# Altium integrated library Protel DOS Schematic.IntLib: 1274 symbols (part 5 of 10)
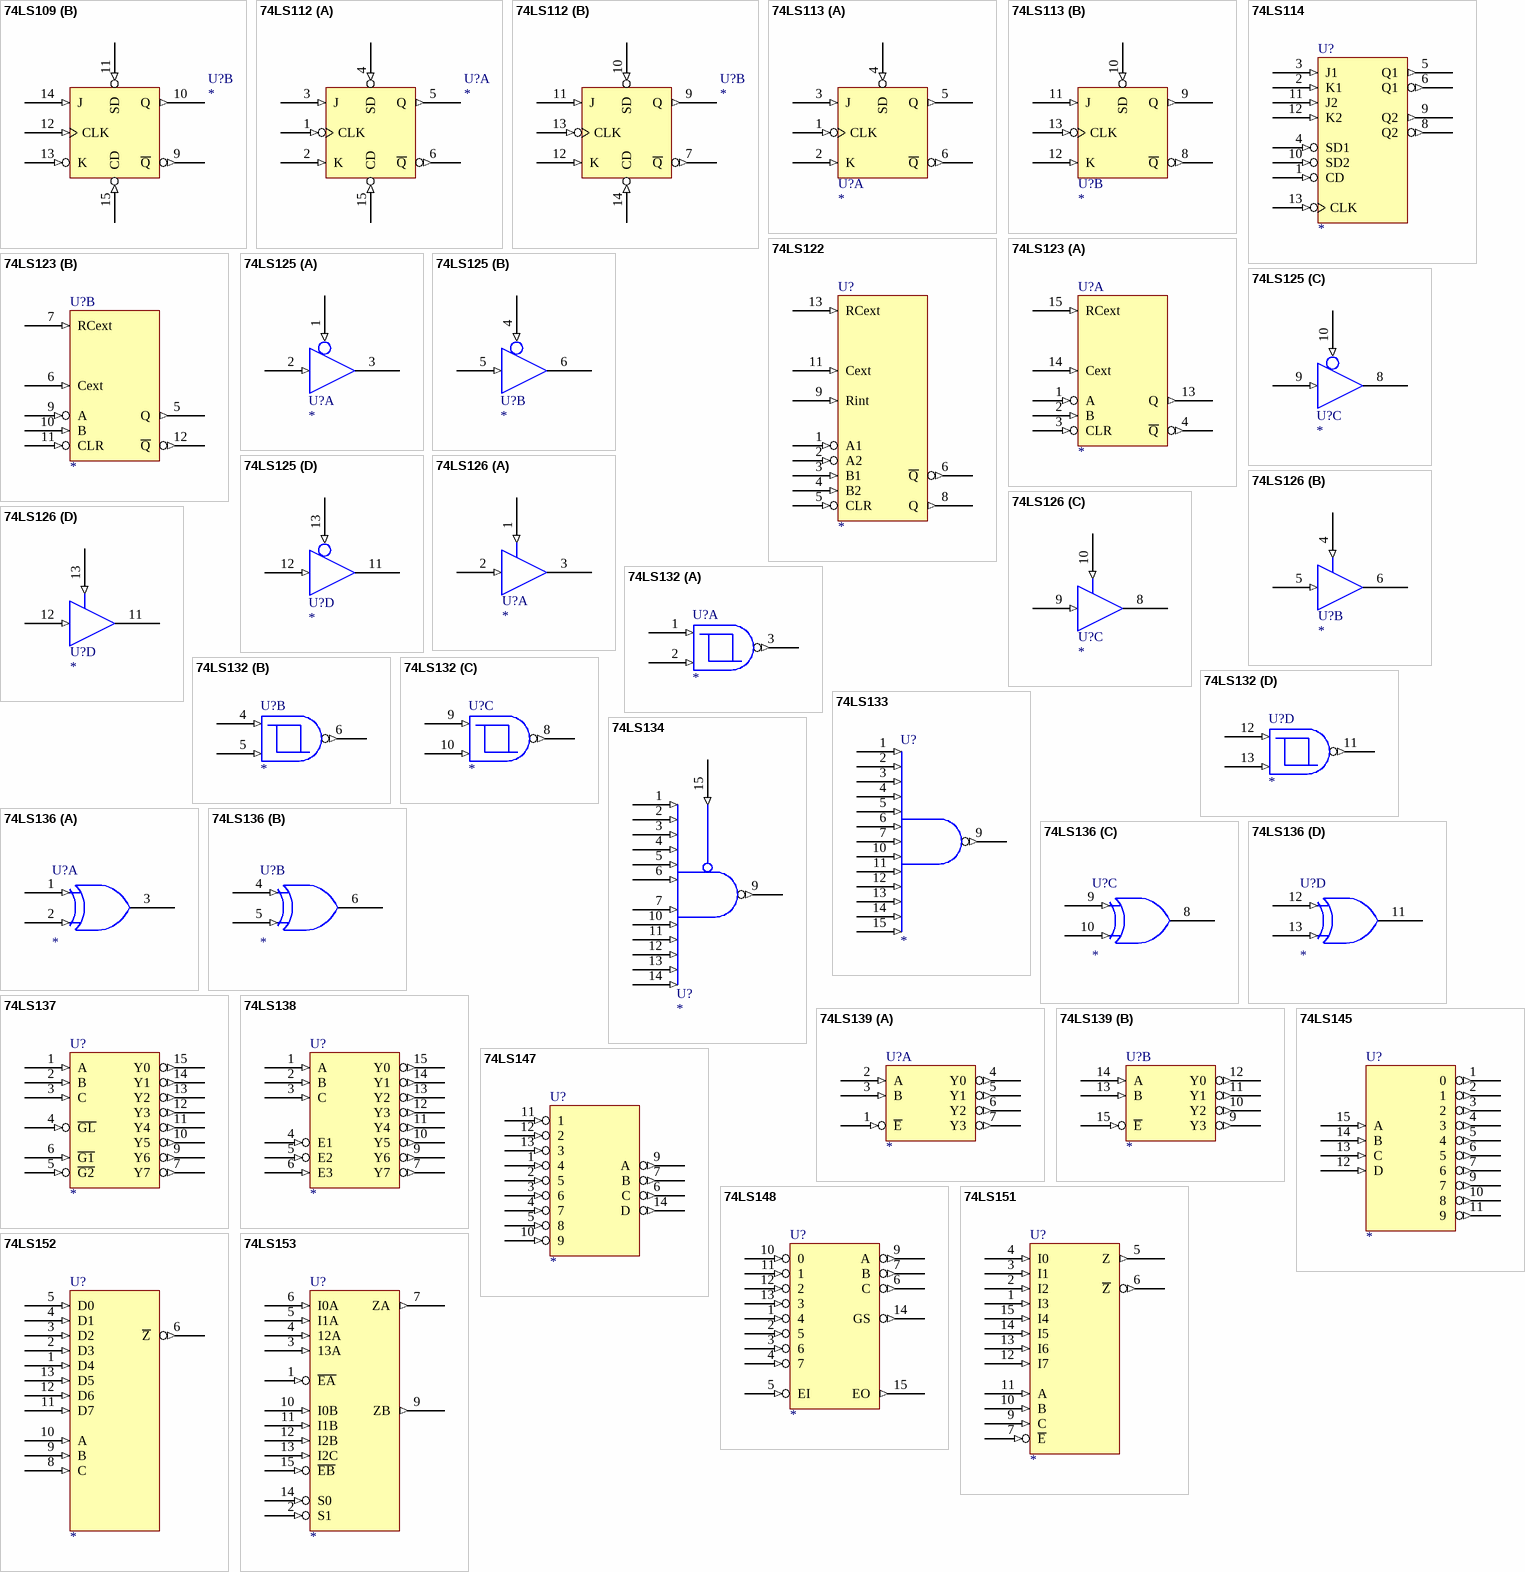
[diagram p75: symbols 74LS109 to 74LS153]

## 74LS125
designator U?
footprint DIP-14
part A pins: 1 (in), 2 (in), 3 (hiz), 7 GND (power) hidden to GND, 14 VCC (power) hidden to VCC
part B pins: 4 (in), 5 (in), 6 (hiz), 7 GND (power) hidden to GND, 14 VCC (power) hidden to VCC
part C pins: 7 GND (power) hidden to GND, 8 (hiz), 9 (in), 10 (in), 14 VCC (power) hidden to VCC
part D pins: 7 GND (power) hidden to GND, 11 (hiz), 12 (in), 13 (in), 14 VCC (power) hidden to VCC
2 alternate drawings of the same symbol

## 74LS126
designator U?
footprint DIP-14
part A pins: 1 (in), 2 (in), 3 (hiz), 7 GND (power) hidden to GND, 14 VCC (power) hidden to VCC
part B pins: 4 (in), 5 (in), 6 (hiz), 7 GND (power) hidden to GND, 14 VCC (power) hidden to VCC
part C pins: 7 GND (power) hidden to GND, 8 (hiz), 9 (in), 10 (in), 14 VCC (power) hidden to VCC
part D pins: 7 GND (power) hidden to GND, 11 (hiz), 12 (in), 13 (in), 14 VCC (power) hidden to VCC
2 alternate drawings of the same symbol

## 74LS132
designator U?
footprint DIP-14
part A pins: 1 (in), 2 (in), 3 (out), 7 GND (power) hidden to GND, 14 VCC (power) hidden to VCC
part B pins: 4 (in), 5 (in), 6 (out), 7 GND (power) hidden to GND, 14 VCC (power) hidden to VCC
part C pins: 7 GND (power) hidden to GND, 8 (out), 9 (in), 10 (in), 14 VCC (power) hidden to VCC
part D pins: 7 GND (power) hidden to GND, 11 (out), 12 (in), 13 (in), 14 VCC (power) hidden to VCC
2 alternate drawings of the same symbol

## 74LS133
designator U?
footprint DIP-16
pins: 1 (in), 2 (in), 3 (in), 4 (in), 5 (in), 6 (in), 7 (in), 8 GND (power) hidden to GND, 9 (out), 10 (in), 11 (in), 12 (in), 13 (in), 14 (in), 15 (in), 16 VCC (power) hidden to VCC
2 alternate drawings of the same symbol

## 74LS134
designator U?
footprint DIP-16
pins: 1 (in), 2 (in), 3 (in), 4 (in), 5 (in), 6 (in), 7 (in), 8 GND (power) hidden to GND, 9 (out), 10 (in), 11 (in), 12 (in), 13 (in), 14 (in), 15 (in), 16 VCC (power) hidden to VCC
2 alternate drawings of the same symbol

## 74LS136
designator U?
footprint DIP-14
part A pins: 1 (in), 2 (in), 3 (oc), 7 GND (power) hidden to GND, 14 VCC (power) hidden to VCC
part B pins: 4 (in), 5 (in), 6 (oc), 7 GND (power) hidden to GND, 14 VCC (power) hidden to VCC
part C pins: 7 GND (power) hidden to GND, 8 (oc), 9 (in), 10 (in), 14 VCC (power) hidden to VCC
part D pins: 7 GND (power) hidden to GND, 11 (oc), 12 (in), 13 (in), 14 VCC (power) hidden to VCC
2 alternate drawings of the same symbol

## 74LS137
designator U?
footprint DIP-16
pins: 1 A (in), 2 B (in), 3 C (in), 4 ~{GL} (in), 5 ~{G2} (in), 6 ~{G1} (in), 7 Y7 (out), 8 GND (power) hidden to GND, 9 Y6 (out), 10 Y5 (out), 11 Y4 (out), 12 Y3 (out), 13 Y2 (out), 14 Y1 (out), 15 Y0 (out), 16 VCC (power) hidden to VCC
2 alternate drawings of the same symbol

## 74LS138
designator U?
footprint DIP-16
pins: 1 A (in), 2 B (in), 3 C (in), 4 E1 (in), 5 E2 (in), 6 E3 (in), 7 Y7 (out), 8 GND (power) hidden to GND, 9 Y6 (out), 10 Y5 (out), 11 Y4 (out), 12 Y3 (out), 13 Y2 (out), 14 Y1 (out), 15 Y0 (out), 16 VCC (power) hidden to VCC
2 alternate drawings of the same symbol

## 74LS139
designator U?
footprint DIP-16
part A pins: 1 ~{E} (in), 2 A (in), 3 B (in), 4 Y0 (out), 5 Y1 (out), 6 Y2 (out), 7 Y3 (out), 8 GND (power) hidden to GND, 16 VCC (power) hidden to VCC
part B pins: 8 GND (power) hidden to GND, 9 Y3 (out), 10 Y2 (out), 11 Y1 (out), 12 Y0 (out), 13 B (in), 14 A (in), 15 ~{E} (in), 16 VCC (power) hidden to VCC
2 alternate drawings of the same symbol

## 74LS145
designator U?
footprint DIP-16
pins: 1 0 (out), 2 1 (out), 3 2 (out), 4 3 (out), 5 4 (out), 6 5 (out), 7 6 (out), 8 GND (power) hidden to GND, 9 7 (out), 10 8 (out), 11 9 (out), 12 D (in), 13 C (in), 14 B (in), 15 A (in), 16 VCC (power) hidden to VCC
2 alternate drawings of the same symbol

## 74LS147
designator U?
footprint DIP-16
pins: 1 4 (in), 2 5 (in), 3 6 (in), 4 7 (in), 5 8 (in), 6 C (out), 7 B (out), 8 GND (power) hidden to GND, 9 A (out), 10 9 (in), 11 1 (in), 12 2 (in), 13 3 (in), 14 D (out), 16 VCC (power) hidden to VCC
2 alternate drawings of the same symbol

## 74LS148
designator U?
footprint DIP-16
pins: 1 4 (in), 2 5 (in), 3 6 (in), 4 7 (in), 5 EI (in), 6 C (out), 7 B (out), 8 GND (power) hidden to GND, 9 A (out), 10 0 (in), 11 1 (in), 12 2 (in), 13 3 (in), 14 GS (out), 15 EO (out), 16 VCC (power) hidden to VCC
2 alternate drawings of the same symbol

## 74LS151
designator U?
footprint DIP-16
pins: 1 I3 (in), 2 I2 (in), 3 I1 (in), 4 I0 (in), 5 Z (out), 6 ~{Z} (out), 7 ~{E} (in), 8 GND (power) hidden to GND, 9 C (in), 10 B (in), 11 A (in), 12 I7 (in), 13 I6 (in), 14 I5 (in), 15 I4 (in), 16 VCC (power) hidden to VCC
2 alternate drawings of the same symbol

## 74LS152
designator U?
footprint DIP-14
pins: 1 D4 (in), 2 D3 (in), 3 D2 (in), 4 D1 (in), 5 D0 (in), 6 ~{Z} (out), 7 GND (power) hidden to GND, 8 C (in), 9 B (in), 10 A (in), 11 D7 (in), 12 D6 (in), 13 D5 (in), 14 VCC (power) hidden to VCC
2 alternate drawings of the same symbol

## 74LS153
designator U?
footprint DIP-16
pins: 1 ~{EA} (in), 2 S1 (in), 3 13A (in), 4 12A (in), 5 I1A (in), 6 I0A (in), 7 ZA (out), 8 GND (power) hidden to GND, 9 ZB (out), 10 I0B (in), 11 I1B (in), 12 I2B (in), 13 I2C (in), 14 S0 (in), 15 ~{EB} (in), 16 VCC (power) hidden to VCC
2 alternate drawings of the same symbol

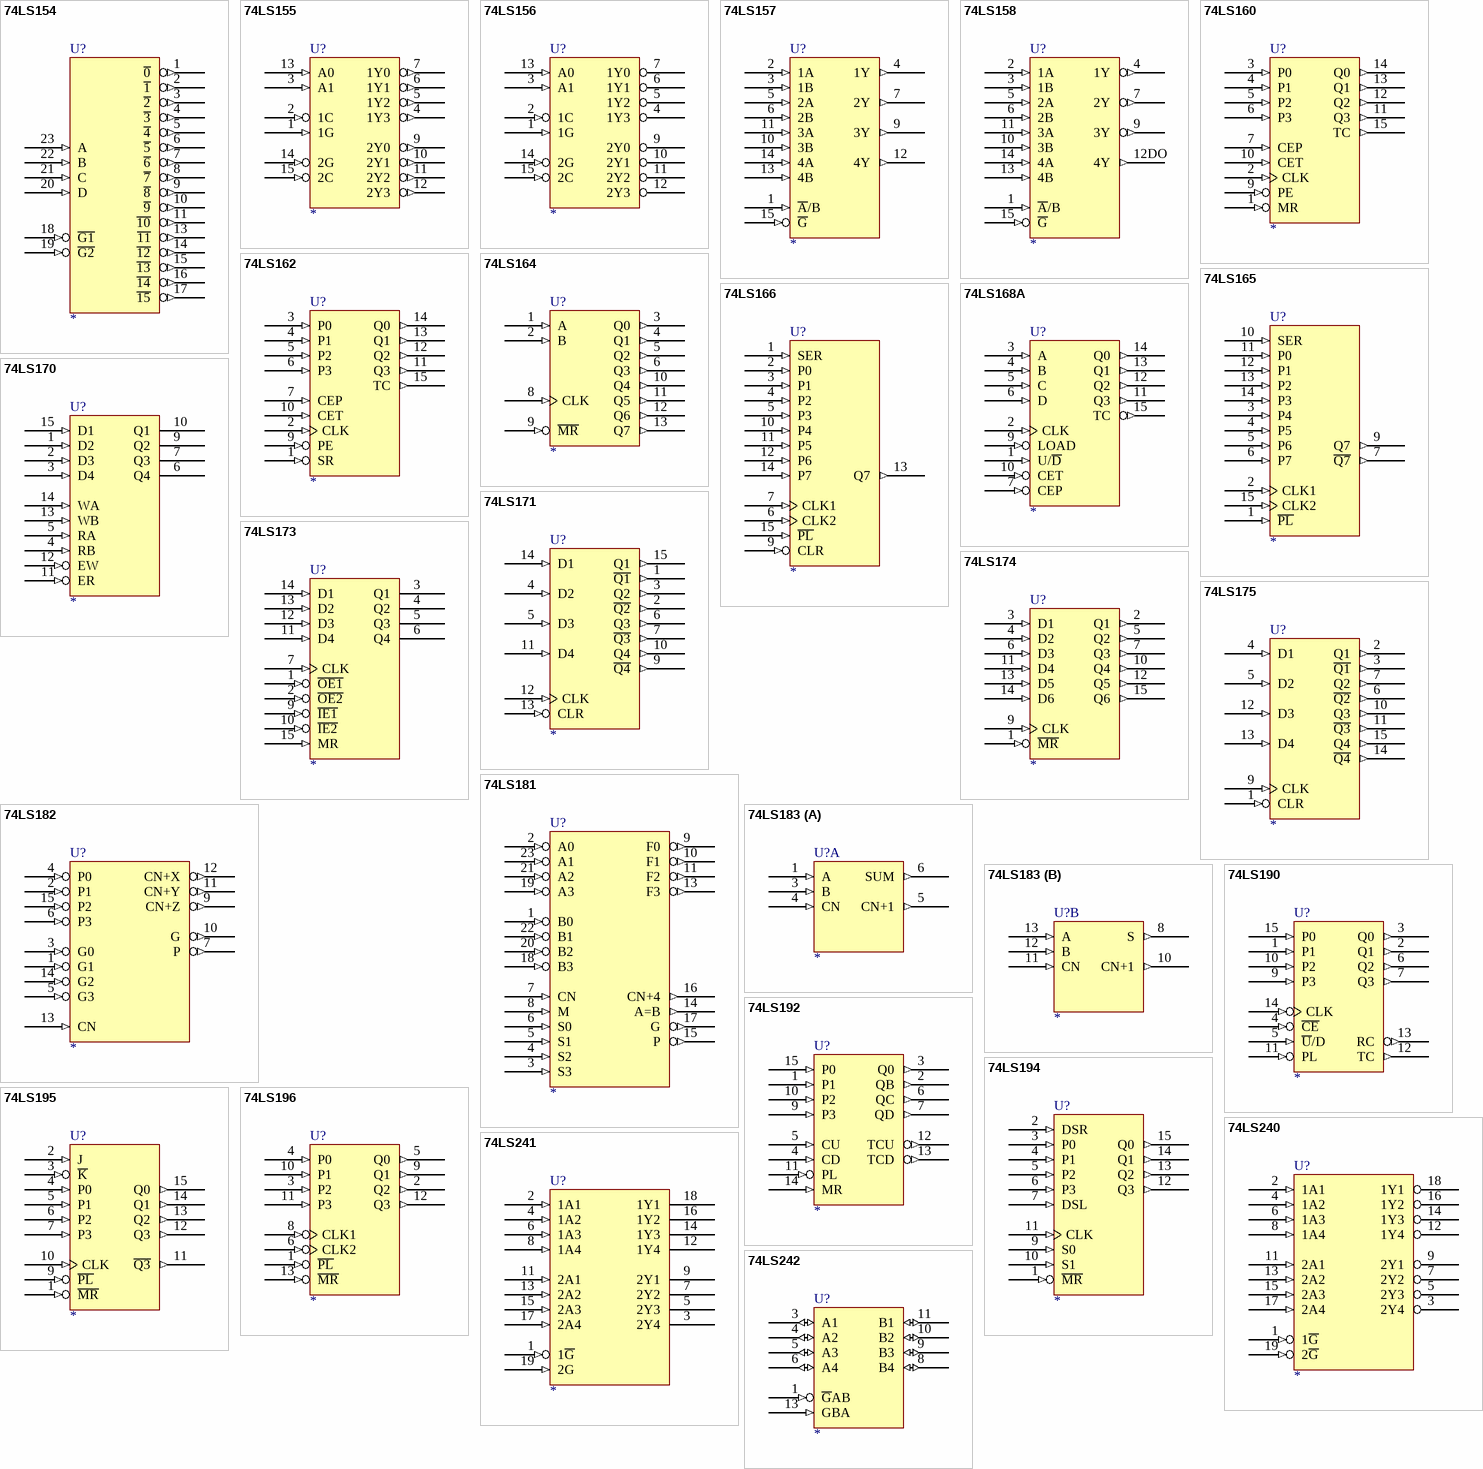
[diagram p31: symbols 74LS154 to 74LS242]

## 74LS154
designator U?
footprint DIP-24
pins: 1 ~{0} (out), 2 ~{1} (out), 3 ~{2} (out), 4 ~{3} (out), 5 ~{4} (out), 6 ~{5} (out), 7 ~{6} (out), 8 ~{7} (out), 9 ~{8} (out), 10 ~{9} (out), 11 ~{10} (out), 12 GND (power) hidden to GND, 13 ~{11} (out), 14 ~{12} (out), 15 ~{13} (out), 16 ~{14} (out), 17 ~{15} (out), 18 ~{G1} (in), 19 ~{G2} (in), 20 D (in), 21 C (in), 22 B (in), 23 A (in), 24 VCC (power) hidden to VCC
2 alternate drawings of the same symbol

## 74LS155
designator U?
footprint DIP-16
pins: 1 1G (in), 2 1C (in), 3 A1 (in), 4 1Y3 (out), 5 1Y2 (out), 6 1Y1 (out), 7 1Y0 (out), 8 GND (power) hidden to GND, 9 2Y0 (out), 10 2Y1 (out), 11 2Y2 (out), 12 2Y3 (out), 13 A0 (in), 14 2G (in), 15 2C (in), 16 VCC (power) hidden to VCC
2 alternate drawings of the same symbol

## 74LS156
designator U?
footprint DIP-16
pins: 1 1G (in), 2 1C (in), 3 A1 (in), 4 1Y3 (oc), 5 1Y2 (oc), 6 1Y1 (oc), 7 1Y0 (oc), 8 GND (power) hidden to GND, 9 2Y0 (oc), 10 2Y1 (oc), 11 2Y2 (oc), 12 2Y3 (oc), 13 A0 (in), 14 2G (in), 15 2C (in), 16 VCC (power) hidden to VCC
2 alternate drawings of the same symbol

## 74LS157
designator U?
footprint DIP-16
pins: 1 ~{A}/B (in), 2 1A (in), 3 1B (in), 4 1Y (out), 5 2A (in), 6 2B (in), 7 2Y (out), 8 GND (power) hidden to GND, 9 3Y (out), 10 3B (in), 11 3A (in), 12 4Y (out), 13 4B (in), 14 4A (in), 15 ~{G} (in), 16 VCC (power) hidden to VCC
2 alternate drawings of the same symbol

## 74LS158
designator U?
footprint DIP-16
pins: 1 ~{A}/B (in), 2 1A (in), 3 1B (in), 4 1Y (out), 5 2A (in), 6 2B (in), 7 2Y (out), 8 GND (power) hidden to GND, 9 3Y (out), 10 3B (in), 11 3A (in), 12DO 4Y (out), 13 4B (in), 14 4A (in), 15 ~{G} (in), 16 VCC (power) hidden to VCC
2 alternate drawings of the same symbol

## 74LS160
designator U?
footprint DIP-16
pins: 1 MR (in), 2 CLK (in), 3 P0 (in), 4 P1 (in), 5 P2 (in), 6 P3 (in), 7 CEP (in), 8 GND (power) hidden to GND, 9 PE (in), 10 CET (in), 11 Q3 (out), 12 Q2 (out), 13 Q1 (out), 14 Q0 (out), 15 TC (out), 16 VCC (power) hidden to VCC
2 alternate drawings of the same symbol

## 74LS162
designator U?
footprint DIP-16
pins: 1 SR (in), 2 CLK (in), 3 P0 (in), 4 P1 (in), 5 P2 (in), 6 P3 (in), 7 CEP (in), 8 GND (power) hidden to GND, 9 PE (in), 10 CET (in), 11 Q3 (out), 12 Q2 (out), 13 Q1 (out), 14 Q0 (out), 15 TC (out), 16 VCC (power) hidden to VCC
2 alternate drawings of the same symbol

## 74LS164
designator U?
footprint DIP-14
pins: 1 A (in), 2 B (in), 3 Q0 (out), 4 Q1 (out), 5 Q2 (out), 6 Q3 (out), 7 GND (power) hidden to GND, 8 CLK (in), 9 ~{MR} (in), 10 Q4 (out), 11 Q5 (out), 12 Q6 (out), 13 Q7 (out), 14 VCC (power) hidden to VCC
2 alternate drawings of the same symbol

## 74LS165
designator U?
footprint DIP-16
pins: 1 ~{PL} (in), 2 CLK1 (in), 3 P4 (in), 4 P5 (in), 5 P6 (in), 6 P7 (in), 7 ~{Q7} (out), 8 GND (power) hidden to GND, 9 Q7 (out), 10 SER (in), 11 P0 (in), 12 P1 (in), 13 P2 (in), 14 P3 (in), 15 CLK2 (in), 16 VCC (power) hidden to VCC
2 alternate drawings of the same symbol

## 74LS166
designator U?
footprint DIP-16
pins: 1 SER (in), 2 P0 (in), 3 P1 (in), 4 P2 (in), 5 P3 (in), 6 CLK2 (in), 7 CLK1 (in), 8 GND (power) hidden to GND, 9 CLR (in), 10 P4 (in), 11 P5 (in), 12 P6 (in), 13 Q7 (out), 14 P7 (in), 15 ~{PL} (in), 16 VCC (power) hidden to VCC
2 alternate drawings of the same symbol

## 74LS168A
designator U?
Synchronous 4-Bit Up/Down Decade Counter
pins: 1 U/~{D} (in), 2 CLK (in), 3 A (in), 4 B (in), 5 C (in), 6 D (in), 7 CEP (in), 8 GND (power) hidden to GND, 9 LOAD (in), 10 CET (in), 11 Q3 (out), 12 Q2 (out), 13 Q1 (out), 14 Q0 (out), 15 TC (out), 16 VCC (power) hidden to VCC
2 alternate drawings of the same symbol

## 74LS170
designator U?
footprint DIP-16
pins: 1 D2 (in), 2 D3 (in), 3 D4 (in), 4 RB (in), 5 RA (in), 6 Q4 (oc), 7 Q3 (oc), 8 GND (power) hidden to GND, 9 Q2 (oc), 10 Q1 (oc), 11 ER (in), 12 EW (in), 13 WB (in), 14 WA (in), 15 D1 (in), 16 VCC (power) hidden to VCC
2 alternate drawings of the same symbol

## 74LS171
designator U?
footprint DIP-16
pins: 1 ~{Q1} (out), 2 ~{Q2} (out), 3 Q2 (out), 4 D2 (in), 5 D3 (in), 6 Q3 (out), 7 ~{Q3} (out), 8 GND (power) hidden to GND, 9 ~{Q4} (out), 10 Q4 (out), 11 D4 (in), 12 CLK (in), 13 CLR (in), 14 D1 (in), 15 Q1 (out), 16 VCC (power) hidden to VCC
2 alternate drawings of the same symbol

## 74LS173
designator U?
footprint DIP-16
pins: 1 ~{OE1} (in), 2 ~{OE2} (in), 3 Q1 (hiz), 4 Q2 (hiz), 5 Q3 (hiz), 6 Q4 (hiz), 7 CLK (in), 8 GND (power) hidden to GND, 9 ~{IE1} (in), 10 ~{IE2} (in), 11 D4 (in), 12 D3 (in), 13 D2 (in), 14 D1 (in), 15 MR (in), 16 VCC (power) hidden to VCC
2 alternate drawings of the same symbol

## 74LS174
designator U?
footprint DIP-16
pins: 1 ~{MR} (in), 2 Q1 (out), 3 D1 (in), 4 D2 (in), 5 Q2 (out), 6 D3 (in), 7 Q3 (out), 8 GND (power) hidden to GND, 9 CLK (in), 10 Q4 (out), 11 D4 (in), 12 Q5 (out), 13 D5 (in), 14 D6 (in), 15 Q6 (out), 16 VCC (power) hidden to VCC
2 alternate drawings of the same symbol

## 74LS175
designator U?
footprint DIP-16
pins: 1 CLR (in), 2 Q1 (out), 3 ~{Q1} (out), 4 D1 (in), 5 D2 (in), 6 ~{Q2} (out), 7 Q2 (out), 8 GND (power) hidden to GND, 9 CLK (in), 10 Q3 (out), 11 ~{Q3} (out), 12 D3 (in), 13 D4 (in), 14 ~{Q4} (out), 15 Q4 (out), 16 VCC (power) hidden to VCC
2 alternate drawings of the same symbol

## 74LS181
designator U?
footprint DIP-24
pins: 1 B0 (in), 2 A0 (in), 3 S3 (in), 4 S2 (in), 5 S1 (in), 6 S0 (in), 7 CN (in), 8 M (in), 9 F0 (out), 10 F1 (out), 11 F2 (out), 12 GND (power) hidden to GND, 13 F3 (out), 14 A=B (out), 15 P (out), 16 CN+4 (out), 17 G (out), 18 B3 (in), 19 A3 (in), 20 B2 (in), 21 A2 (in), 22 B1 (in), 23 A1 (in), 24 VCC (power) hidden to VCC
2 alternate drawings of the same symbol

## 74LS182
designator U?
footprint DIP-16
pins: 1 G1 (in), 2 P1 (in), 3 G0 (in), 4 P0 (in), 5 G3 (in), 6 P3 (in), 7 P (out), 8 GND (power) hidden to GND, 9 CN+Z (out), 10 G (out), 11 CN+Y (out), 12 CN+X (out), 13 CN (in), 14 G2 (in), 15 P2 (in), 16 VCC (power) hidden to VCC
2 alternate drawings of the same symbol

## 74LS183
designator U?
footprint DIP-14
part A pins: 1 A (in), 3 B (in), 4 CN (in), 5 CN+1 (out), 6 SUM (out), 7 GND (power) hidden to GND, 14 VCC (power) hidden to VCC
part B pins: 7 GND (power) hidden to GND, 8 S (out), 10 CN+1 (out), 11 CN (in), 12 B (in), 13 A (in), 14 VCC (power) hidden to VCC
2 alternate drawings of the same symbol

## 74LS190
designator U?
footprint DIP-16
pins: 1 P1 (in), 2 Q1 (out), 3 Q0 (out), 4 ~{CE} (in), 5 ~{U}/D (in), 6 Q2 (out), 7 Q3 (out), 8 GND (power) hidden to GND, 9 P3 (in), 10 P2 (in), 11 PL (in), 12 TC (out), 13 RC (out), 14 CLK (in), 15 P0 (in), 16 VCC (power) hidden to VCC
2 alternate drawings of the same symbol

## 74LS192
designator U?
footprint DIP-16
pins: 1 P1 (in), 2 QB (out), 3 Q0 (out), 4 CD (in), 5 CU (in), 6 QC (out), 7 QD (out), 8 GND (power) hidden to GND, 9 P3 (in), 10 P2 (in), 11 PL (in), 12 TCU (out), 13 TCD (out), 14 MR (in), 15 P0 (in), 16 VCC (power) hidden to VCC
2 alternate drawings of the same symbol

## 74LS194
designator U?
footprint DIP-16
pins: 1 ~{MR} (in), 2 DSR (in), 3 P0 (in), 4 P1 (in), 5 P2 (in), 6 P3 (in), 7 DSL (in), 8 GND (power) hidden to GND, 9 S0 (in), 10 S1 (in), 11 CLK (in), 12 Q3 (out), 13 Q2 (out), 14 Q1 (out), 15 Q0 (out), 16 VCC (power) hidden to VCC
2 alternate drawings of the same symbol

## 74LS195
designator U?
footprint DIP-16
pins: 1 ~{MR} (in), 2 J (in), 3 ~{K} (in), 4 P0 (in), 5 P1 (in), 6 P2 (in), 7 P3 (in), 8 GND (power) hidden to GND, 9 ~{PL} (in), 10 CLK (in), 11 ~{Q3} (out), 12 Q3 (out), 13 Q2 (out), 14 Q1 (out), 15 Q0 (out), 16 VCC (power) hidden to VCC
2 alternate drawings of the same symbol

## 74LS196
designator U?
footprint DIP-16
pins: 1 ~{PL} (in), 2 Q2 (out), 3 P2 (in), 4 P0 (in), 5 Q0 (out), 6 CLK2 (in), 7 GND (power) hidden to GND, 8 CLK1 (in), 9 Q1 (out), 10 P1 (in), 11 P3 (in), 12 Q3 (out), 13 ~{MR} (in), 14 VCC (power) hidden to VCC
2 alternate drawings of the same symbol

## 74LS240
designator U?
footprint DIP-16
pins: 1 1~{G} (in), 2 1A1 (in), 3 2Y4 (hiz), 4 1A2 (in), 5 2Y3 (hiz), 6 1A3 (in), 7 2Y2 (hiz), 8 1A4 (in), 9 2Y1 (hiz), 10 GND (power) hidden to GND, 11 2A1 (in), 12 1Y4 (hiz), 13 2A2 (in), 14 1Y3 (hiz), 15 2A3 (in), 16 1Y2 (hiz), 17 2A4 (in), 18 1Y1 (hiz), 19 2~{G} (in), 20 VCC (power) hidden to VCC
2 alternate drawings of the same symbol

## 74LS241
designator U?
footprint DIP-20
pins: 1 1~{G} (in), 2 1A1 (in), 3 2Y4 (hiz), 4 1A2 (in), 5 2Y3 (hiz), 6 1A3 (in), 7 2Y2 (hiz), 8 1A4 (in), 9 2Y1 (hiz), 10 GND (power) hidden to GND, 11 2A1 (in), 12 1Y4 (hiz), 13 2A2 (in), 14 1Y3 (hiz), 15 2A3 (in), 16 1Y2 (hiz), 17 2A4 (in), 18 1Y1 (hiz), 19 2G (in), 20 VCC (power) hidden to VCC
2 alternate drawings of the same symbol

## 74LS242
designator U?
footprint DIP-14
pins: 1 ~{G}AB (in), 3 A1 (io), 4 A2 (io), 5 A3 (io), 6 A4 (io), 7 GND (power) hidden to GND, 8 B4 (io), 9 B3 (io), 10 B2 (io), 11 B1 (io), 13 GBA (in), 14 VCC (power) hidden to VCC
2 alternate drawings of the same symbol

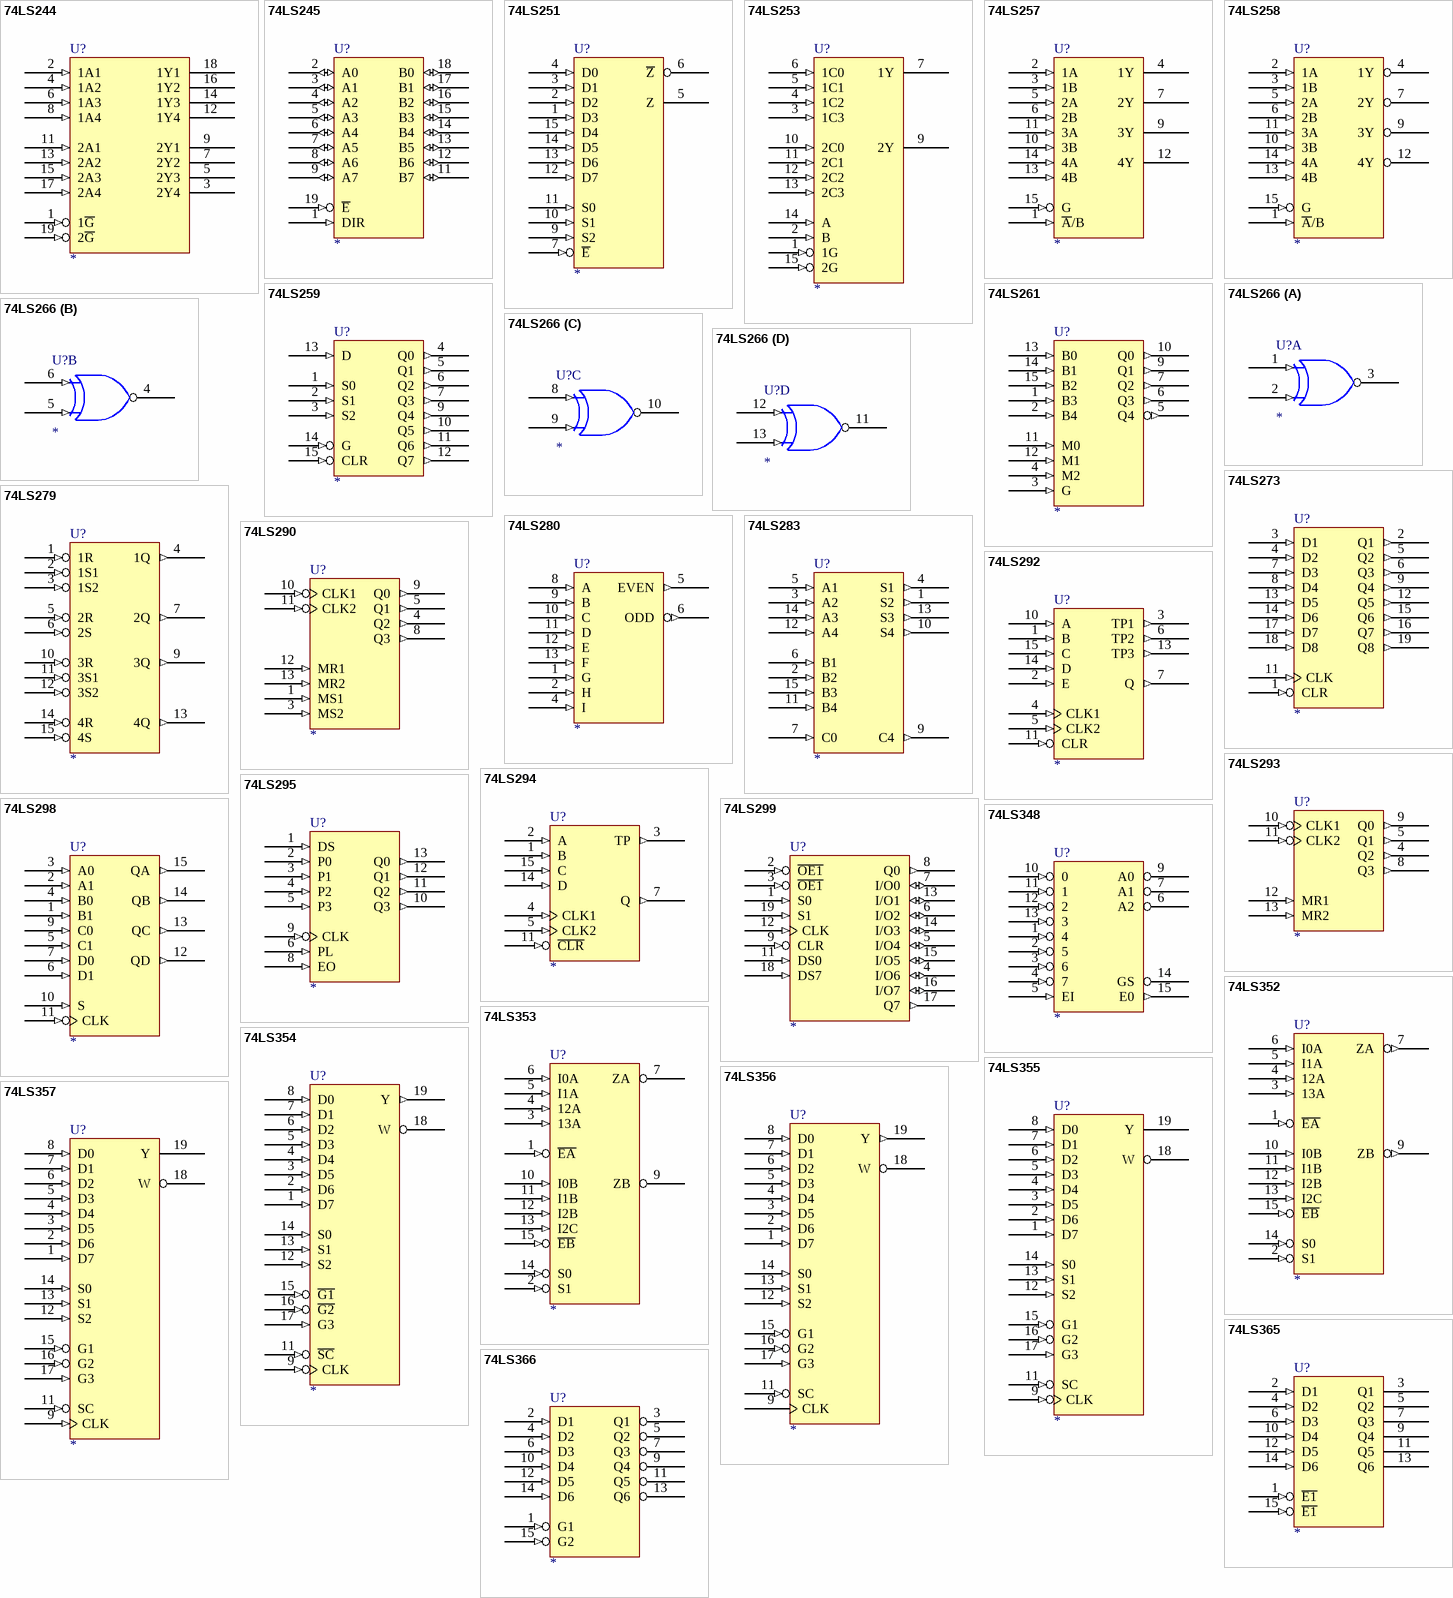
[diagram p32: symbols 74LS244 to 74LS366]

## 74LS244
designator U?
footprint DIP-20
pins: 1 1~{G} (in), 2 1A1 (in), 3 2Y4 (hiz), 4 1A2 (in), 5 2Y3 (hiz), 6 1A3 (in), 7 2Y2 (hiz), 8 1A4 (in), 9 2Y1 (hiz), 10 GND (power) hidden to GND, 11 2A1 (in), 12 1Y4 (hiz), 13 2A2 (in), 14 1Y3 (hiz), 15 2A3 (in), 16 1Y2 (hiz), 17 2A4 (in), 18 1Y1 (hiz), 19 2~{G} (in), 20 VCC (power) hidden to VCC
2 alternate drawings of the same symbol

## 74LS245
designator U?
footprint DIP-20
pins: 1 DIR (in), 2 A0 (io), 3 A1 (io), 4 A2 (io), 5 A3 (io), 6 A4 (io), 7 A5 (io), 8 A6 (io), 9 A7 (io), 10 GND (power) hidden to GND, 11 B7 (io), 12 B6 (io), 13 B5 (io), 14 B4 (io), 15 B3 (io), 16 B2 (io), 17 B1 (io), 18 B0 (io), 19 ~{E} (in), 20 VCC (power) hidden to VCC
2 alternate drawings of the same symbol

## 74LS251
designator U?
footprint DIP-16
pins: 1 D3 (in), 2 D2 (in), 3 D1 (in), 4 D0 (in), 5 Z (hiz), 6 ~{Z} (hiz), 7 ~{E} (in), 8 GND (power) hidden to GND, 9 S2 (in), 10 S1 (in), 11 S0 (in), 12 D7 (in), 13 D6 (in), 14 D5 (in), 15 D4 (in), 16 VCC (power) hidden to VCC
2 alternate drawings of the same symbol

## 74LS253
designator U?
footprint DIP-16
pins: 1 1G (in), 2 B (in), 3 1C3 (in), 4 1C2 (in), 5 1C1 (in), 6 1C0 (in), 7 1Y (hiz), 8 GND (power) hidden to GND, 9 2Y (hiz), 10 2C0 (in), 11 2C1 (in), 12 2C2 (in), 13 2C3 (in), 14 A (in), 15 2G (in), 16 VCC (power) hidden to VCC
2 alternate drawings of the same symbol

## 74LS257
designator U?
footprint DIP-16
pins: 1 ~{A}/B (in), 2 1A (in), 3 1B (in), 4 1Y (hiz), 5 2A (in), 6 2B (in), 7 2Y (hiz), 8 GND (power) hidden to GND, 9 3Y (hiz), 10 3B (in), 11 3A (in), 12 4Y (hiz), 13 4B (in), 14 4A (in), 15 G (in), 16 VCC (power) hidden to VCC
2 alternate drawings of the same symbol

## 74LS258
designator U?
footprint DIP-16
pins: 1 ~{A}/B (in), 2 1A (in), 3 1B (in), 4 1Y (hiz), 5 2A (in), 6 2B (in), 7 2Y (hiz), 8 GND (power) hidden to GND, 9 3Y (hiz), 10 3B (in), 11 3A (in), 12 4Y (hiz), 13 4B (in), 14 4A (in), 15 G (in), 16 VCC (power) hidden to VCC
2 alternate drawings of the same symbol

## 74LS259
designator U?
footprint DIP-16
pins: 1 S0 (in), 2 S1 (in), 3 S2 (in), 4 Q0 (out), 5 Q1 (out), 6 Q2 (out), 7 Q3 (out), 8 GND (power) hidden to GND, 9 Q4 (out), 10 Q5 (out), 11 Q6 (out), 12 Q7 (out), 13 D (in), 14 G (in), 15 CLR (in), 16 VCC (power) hidden to VCC
2 alternate drawings of the same symbol

## 74LS261
designator U?
footprint DIP-16
pins: 1 B3 (in), 2 B4 (in), 3 G (in), 4 M2 (in), 5 Q4 (out), 6 Q3 (out), 7 Q2 (out), 8 GND (power) hidden to GND, 9 Q1 (out), 10 Q0 (out), 11 M0 (in), 12 M1 (in), 13 B0 (in), 14 B1 (in), 15 B2 (in), 16 VCC (power) hidden to VCC
2 alternate drawings of the same symbol

## 74LS266
designator U?
footprint DIP-14
part A pins: 1 (in), 2 (in), 3 (oc), 7 GND (power) hidden to GND, 14 VCC (power) hidden to VCC
part B pins: 4 (oc), 5 (in), 6 (in), 7 GND (power) hidden to GND, 14 VCC (power) hidden to VCC
part C pins: 7 GND (power) hidden to GND, 8 (in), 9 (in), 10 (oc), 14 VCC (power) hidden to VCC
part D pins: 7 GND (power) hidden to GND, 11 (oc), 12 (in), 13 (in), 14 VCC (power) hidden to VCC
2 alternate drawings of the same symbol

## 74LS273
designator U?
footprint DIP-20
pins: 1 CLR (in), 2 Q1 (out), 3 D1 (in), 4 D2 (in), 5 Q2 (out), 6 Q3 (out), 7 D3 (in), 8 D4 (in), 9 Q4 (out), 10 GND (power) hidden to GND, 11 CLK (in), 12 Q5 (out), 13 D5 (in), 14 D6 (in), 15 Q6 (out), 16 Q7 (out), 17 D7 (in), 18 D8 (in), 19 Q8 (out), 20 VCC (power) hidden to VCC
2 alternate drawings of the same symbol

## 74LS279
designator U?
footprint DIP-16
pins: 1 1R (in), 2 1S1 (in), 3 1S2 (in), 4 1Q (out), 5 2R (in), 6 2S (in), 7 2Q (out), 8 GND (power) hidden to GND, 9 3Q (out), 10 3R (in), 11 3S1 (in), 12 3S2 (in), 13 4Q (out), 14 4R (in), 15 4S (in), 16 VCC (power) hidden to VCC
2 alternate drawings of the same symbol

## 74LS280
designator U?
footprint DIP-14
pins: 1 G (in), 2 H (in), 4 I (in), 5 EVEN (out), 6 ODD (out), 7 GND (power) hidden to GND, 8 A (in), 9 B (in), 10 C (in), 11 D (in), 12 E (in), 13 F (in), 14 VCC (power) hidden to VCC
2 alternate drawings of the same symbol

## 74LS283
designator U?
footprint DIP-16
pins: 1 S2 (out), 2 B2 (in), 3 A2 (in), 4 S1 (out), 5 A1 (in), 6 B1 (in), 7 C0 (in), 8 GND (power) hidden to GND, 9 C4 (out), 10 S4 (out), 11 B4 (in), 12 A4 (in), 13 S3 (out), 14 A3 (in), 15 B3 (in), 16 VCC (power) hidden to VCC
2 alternate drawings of the same symbol

## 74LS290
designator U?
footprint DIP-14
pins: 1 MS1 (in), 3 MS2 (in), 4 Q2 (out), 5 Q1 (out), 7 GND (power) hidden to GND, 8 Q3 (out), 9 Q0 (out), 10 CLK1 (in), 11 CLK2 (in), 12 MR1 (in), 13 MR2 (in), 14 VCC (power) hidden to VCC
2 alternate drawings of the same symbol

## 74LS292
designator U?
footprint DIP-16
pins: 1 B (in), 2 E (in), 3 TP1 (out), 4 CLK1 (in), 5 CLK2 (in), 6 TP2 (out), 7 Q (out), 8 GND (power) hidden to GND, 10 A (in), 11 CLR (in), 13 TP3 (out), 14 D (in), 15 C (in), 16 VCC (power) hidden to VCC
2 alternate drawings of the same symbol

## 74LS293
designator U?
footprint DIP-14
pins: 4 Q2 (out), 5 Q1 (out), 7 GND (power) hidden to GND, 8 Q3 (out), 9 Q0 (out), 10 CLK1 (in), 11 CLK2 (in), 12 MR1 (in), 13 MR2 (in), 14 VCC (power) hidden to VCC
2 alternate drawings of the same symbol

## 74LS294
designator U?
footprint DIP-16
pins: 1 B (in), 2 A (in), 3 TP (out), 4 CLK1 (in), 5 CLK2 (in), 7 Q (out), 8 GND (power) hidden to GND, 11 ~{CLR} (in), 14 D (in), 15 C (in), 16 VCC (power) hidden to VCC
2 alternate drawings of the same symbol

## 74LS295
designator U?
footprint DIP-14
pins: 1 DS (in), 2 P0 (in), 3 P1 (in), 4 P2 (in), 5 P3 (in), 6 PL (in), 7 GND (power) hidden to GND, 8 EO (in), 9 CLK (in), 10 Q3 (out), 11 Q2 (out), 12 Q1 (out), 13 Q0 (out), 14 VCC (power) hidden to VCC
2 alternate drawings of the same symbol

## 74LS298
designator U?
footprint DIP-16
pins: 1 B1 (in), 2 A1 (in), 3 A0 (in), 4 B0 (in), 5 C1 (in), 6 D1 (in), 7 D0 (in), 8 GND (power) hidden to GND, 9 C0 (in), 10 S (in), 11 CLK (in), 12 QD (out), 13 QC (out), 14 QB (out), 15 QA (out), 16 VCC (power) hidden to VCC
2 alternate drawings of the same symbol

## 74LS299
designator U?
footprint DIP-20
pins: 1 S0 (in), 2 ~{OE1} (in), 3 ~{OE1} (in), 4 I/O6 (io), 5 I/O4 (io), 6 I/O2 (io), 7 I/O0 (io), 8 Q0 (out), 9 CLR (in), 10 GND (power) hidden to GND, 11 DS0 (in), 12 CLK (in), 13 I/O1 (io), 14 I/O3 (io), 15 I/O5 (io), 16 I/O7 (io), 17 Q7 (out), 18 DS7 (in), 19 S1 (in), 20 VCC (power) hidden to VCC
2 alternate drawings of the same symbol

## 74LS348
designator U?
footprint DIP-16
pins: 1 4 (in), 2 5 (in), 3 6 (in), 4 7 (in), 5 EI (in), 6 A2 (hiz), 7 A1 (hiz), 8 GND (power) hidden to GND, 9 A0 (hiz), 10 0 (in), 11 1 (in), 12 2 (in), 13 3 (in), 14 GS (hiz), 15 E0 (out), 16 VCC (power) hidden to VCC
2 alternate drawings of the same symbol

## 74LS352
designator U?
footprint DIP-16
pins: 1 ~{EA} (in), 2 S1 (in), 3 13A (in), 4 12A (in), 5 I1A (in), 6 I0A (in), 7 ZA (out), 8 GND (power) hidden to GND, 9 ZB (out), 10 I0B (in), 11 I1B (in), 12 I2B (in), 13 I2C (in), 14 S0 (in), 15 ~{EB} (in), 16 VCC (power) hidden to VCC
2 alternate drawings of the same symbol

## 74LS353
designator U?
footprint DIP-16
pins: 1 ~{EA} (in), 2 S1 (in), 3 13A (in), 4 12A (in), 5 I1A (in), 6 I0A (in), 7 ZA (hiz), 8 GND (power) hidden to GND, 9 ZB (hiz), 10 I0B (in), 11 I1B (in), 12 I2B (in), 13 I2C (in), 14 S0 (in), 15 ~{EB} (in), 16 VCC (power) hidden to VCC
2 alternate drawings of the same symbol

## 74LS354
designator U?
footprint DIP-20
pins: 1 D7 (in), 2 D6 (in), 3 D5 (in), 4 D4 (in), 5 D3 (in), 6 D2 (in), 7 D1 (in), 8 D0 (in), 9 CLK (in), 10 GND (power) hidden to GND, 11 ~{SC} (in), 12 S2 (in), 13 S1 (in), 14 S0 (in), 15 ~{G1} (in), 16 ~{G2} (in), 17 G3 (in), 18 W (hiz), 19 Y (out), 20 VCC (power) hidden to VCC
2 alternate drawings of the same symbol

## 74LS355
designator U?
footprint DIP-20
pins: 1 D7 (in), 2 D6 (in), 3 D5 (in), 4 D4 (in), 5 D3 (in), 6 D2 (in), 7 D1 (in), 8 D0 (in), 9 CLK (in), 10 GND (power) hidden to GND, 11 SC (in), 12 S2 (in), 13 S1 (in), 14 S0 (in), 15 G1 (in), 16 G2 (in), 17 G3 (in), 18 W (oc), 19 Y (oc), 20 VCC (power) hidden to VCC
2 alternate drawings of the same symbol

## 74LS356
designator U?
footprint DIP-20
pins: 1 D7 (in), 2 D6 (in), 3 D5 (in), 4 D4 (in), 5 D3 (in), 6 D2 (in), 7 D1 (in), 8 D0 (in), 9 CLK, 10 GND (power) hidden to GND, 11 SC (in), 12 S2 (in), 13 S1 (in), 14 S0 (in), 15 G1 (in), 16 G2 (in), 17 G3 (in), 18 W (hiz), 19 Y (out), 20 VCC (power) hidden to VCC
2 alternate drawings of the same symbol

## 74LS357
designator U?
footprint DIP-20
pins: 1 D7 (in), 2 D6 (in), 3 D5 (in), 4 D4 (in), 5 D3 (in), 6 D2 (in), 7 D1 (in), 8 D0 (in), 9 CLK (in), 10 GND (power) hidden to GND, 11 SC (in), 12 S2 (in), 13 S1 (in), 14 S0 (in), 15 G1 (in), 16 G2 (in), 17 G3 (in), 18 W (oc), 19 Y (oc), 20 VCC (power) hidden to VCC
2 alternate drawings of the same symbol

## 74LS365
designator U?
footprint DIP-16
pins: 1 ~{E1} (in), 2 D1 (in), 3 Q1 (hiz), 4 D2 (in), 5 Q2 (hiz), 6 D3 (in), 7 Q3 (hiz), 8 GND (power) hidden to GND, 9 Q4 (hiz), 10 D4 (in), 11 Q5 (hiz), 12 D5 (in), 13 Q6 (hiz), 14 D6 (in), 15 ~{E1} (in), 16 VCC (power) hidden to VCC
2 alternate drawings of the same symbol

## 74LS366
designator U?
footprint DIP-16
pins: 1 G1 (in), 2 D1 (in), 3 Q1 (hiz), 4 D2 (in), 5 Q2 (hiz), 6 D3 (in), 7 Q3 (hiz), 8 GND (power) hidden to GND, 9 Q4 (hiz), 10 D4 (in), 11 Q5 (hiz), 12 D5 (in), 13 Q6 (hiz), 14 D6 (in), 15 G2 (in), 16 VCC (power) hidden to VCC
2 alternate drawings of the same symbol

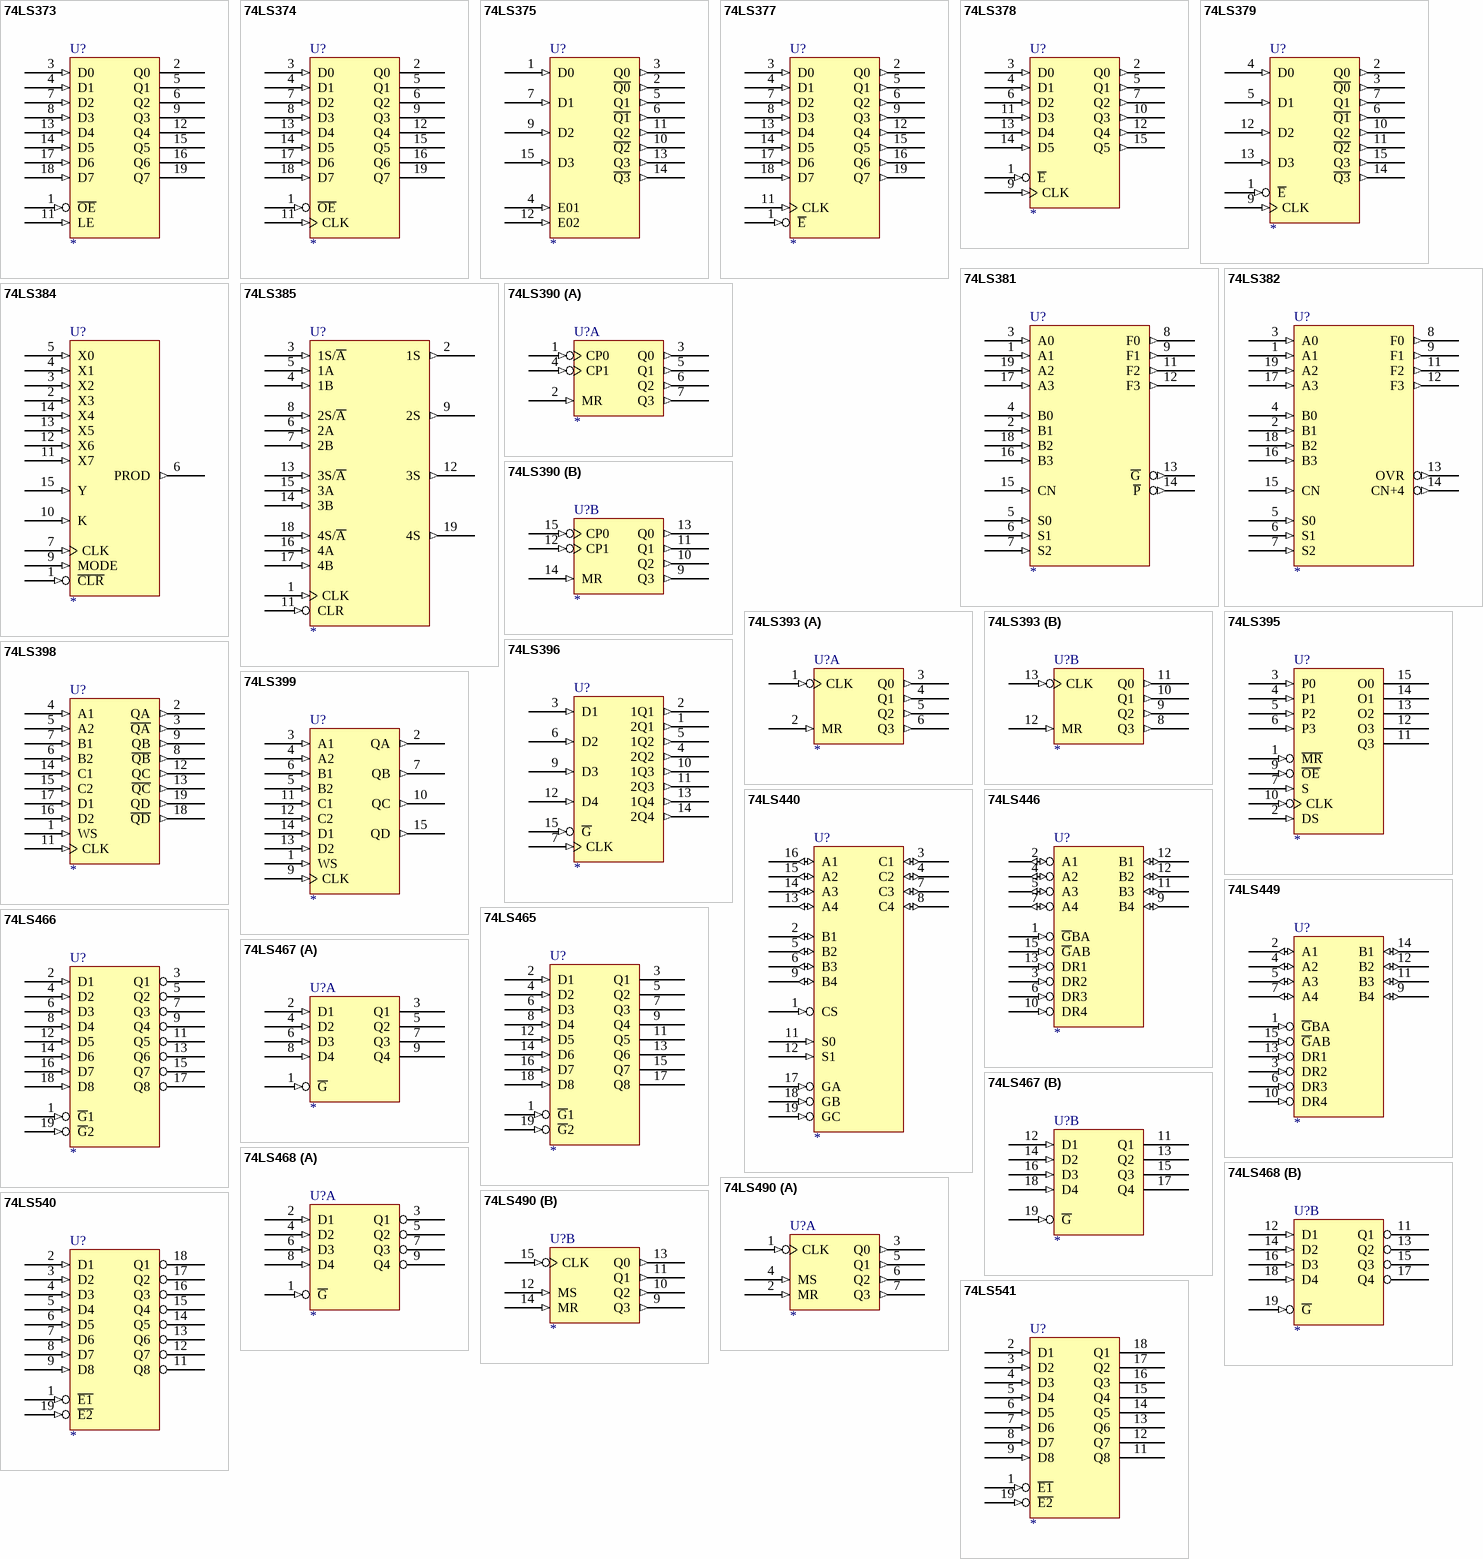
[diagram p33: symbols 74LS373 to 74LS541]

## 74LS373
designator U?
footprint DIP-20
pins: 1 ~{OE} (in), 2 Q0 (hiz), 3 D0 (in), 4 D1 (in), 5 Q1 (hiz), 6 Q2 (hiz), 7 D2 (in), 8 D3 (in), 9 Q3 (hiz), 10 GND (power) hidden to GND, 11 LE (in), 12 Q4 (hiz), 13 D4 (in), 14 D5 (in), 15 Q5 (hiz), 16 Q6 (hiz), 17 D6 (in), 18 D7 (in), 19 Q7 (hiz), 20 VCC (power) hidden to VCC
2 alternate drawings of the same symbol

## 74LS374
designator U?
footprint DIP-20
pins: 1 ~{OE} (in), 2 Q0 (hiz), 3 D0 (in), 4 D1 (in), 5 Q1 (hiz), 6 Q2 (hiz), 7 D2 (in), 8 D3 (in), 9 Q3 (hiz), 10 GND (power) hidden to GND, 11 CLK (in), 12 Q4 (hiz), 13 D4 (in), 14 D5 (in), 15 Q5 (hiz), 16 Q6 (hiz), 17 D6 (in), 18 D7 (in), 19 Q7 (hiz), 20 VCC (power) hidden to VCC
2 alternate drawings of the same symbol

## 74LS375
designator U?
footprint DIP-16
pins: 1 D0 (in), 2 ~{Q0} (out), 3 Q0 (out), 4 E01 (in), 5 Q1 (out), 6 ~{Q1} (out), 7 D1 (in), 8 GND (power) hidden to GND, 9 D2 (in), 10 ~{Q2} (out), 11 Q2 (out), 12 E02 (in), 13 Q3 (out), 14 ~{Q3} (out), 15 D3 (in), 16 VCC (power) hidden to VCC
2 alternate drawings of the same symbol

## 74LS377
designator U?
footprint DIP-16
pins: 1 ~{E} (in), 2 Q0 (out), 3 D0 (in), 4 D1 (in), 5 Q1 (out), 6 Q2 (out), 7 D2 (in), 8 D3 (in), 9 Q3 (out), 11 CLK (in), 11 GND (power) hidden to GND, 12 Q4 (out), 13 D4 (in), 14 D5 (in), 15 Q5 (out), 16 Q6 (out), 17 D6 (in), 18 D7 (in), 19 Q7 (out), 21 VCC (power) hidden to VCC
2 alternate drawings of the same symbol

## 74LS378
designator U?
footprint DIP-16
pins: 1 ~{E} (in), 2 Q0 (out), 3 D0 (in), 4 D1 (in), 5 Q1 (out), 6 D2 (in), 7 Q2 (out), 8 GND (power) hidden to GND, 9 CLK (in), 10 Q3 (out), 11 D3 (in), 12 Q4 (out), 13 D4 (in), 14 D5 (in), 15 Q5 (out), 16 VCC (power) hidden to VCC
2 alternate drawings of the same symbol

## 74LS379
designator U?
footprint DIP-16
pins: 1 ~{E} (in), 2 Q0 (out), 3 ~{Q0} (out), 4 D0 (in), 5 D1 (in), 6 ~{Q1} (out), 7 Q1 (out), 8 GND (power) hidden to GND, 9 CLK (in), 10 Q2 (out), 11 ~{Q2} (out), 12 D2 (in), 13 D3 (in), 14 ~{Q3} (out), 15 Q3 (out), 16 VCC (power) hidden to VCC
2 alternate drawings of the same symbol

## 74LS381
designator U?
footprint DIP-16
pins: 1 A1 (in), 2 B1 (in), 3 A0 (in), 4 B0 (in), 5 S0 (in), 6 S1 (in), 7 S2 (in), 8 F0 (out), 9 F1 (out), 10 GND (power) hidden to GND, 11 F2 (out), 12 F3 (out), 13 ~{G} (out), 14 ~{P} (out), 15 CN (in), 16 B3 (in), 17 A3 (in), 18 B2 (in), 19 A2 (in), 20 VCC (power) hidden to VCC
2 alternate drawings of the same symbol

## 74LS382
designator U?
footprint DIP-20
pins: 1 A1 (in), 2 B1 (in), 3 A0 (in), 4 B0 (in), 5 S0 (in), 6 S1 (in), 7 S2 (in), 8 F0 (out), 9 F1 (out), 10 GND (power) hidden to GND, 11 F2 (out), 12 F3 (out), 13 OVR (out), 14 CN+4 (out), 15 CN (in), 16 B3 (in), 17 A3 (in), 18 B2 (in), 19 A2 (in), 20 VCC (power) hidden to VCC
2 alternate drawings of the same symbol

## 74LS384
designator U?
footprint DIP-16
pins: 1 ~{CLR} (in), 2 X3 (in), 3 X2 (in), 4 X1 (in), 5 X0 (in), 6 PROD (out), 7 CLK (in), 8 GND (power) hidden to GND, 9 MODE (in), 10 K (in), 11 X7 (in), 12 X6 (in), 13 X5 (in), 14 X4 (in), 15 Y (in), 16 VCC (power) hidden to VCC
2 alternate drawings of the same symbol

## 74LS385
designator U?
footprint DIP-20
pins: 1 CLK (in), 2 1S (out), 3 1S/~{A} (in), 4 1B (in), 5 1A (in), 6 2A (in), 7 2B (in), 8 2S/~{A} (in), 9 2S (out), 10 GND (power) hidden to GND, 11 CLR (in), 12 3S (out), 13 3S/~{A} (in), 14 3B (in), 15 3A (in), 16 4A (in), 17 4B (in), 18 4S/~{A} (in), 19 4S (out), 20 VCC (power) hidden to VCC
2 alternate drawings of the same symbol

## 74LS390
designator U?
footprint DIP-16
part A pins: 1 CP0 (in), 2 MR (in), 3 Q0 (out), 4 CP1 (in), 5 Q1 (out), 6 Q2 (out), 7 Q3 (out), 8 GND (power) hidden to GND, 16 VCC (power) hidden to VCC
part B pins: 8 GND (power) hidden to GND, 9 Q3 (out), 10 Q2 (out), 11 Q1 (out), 12 CP1 (in), 13 Q0 (out), 14 MR (in), 15 CP0 (in), 16 VCC (power) hidden to VCC
2 alternate drawings of the same symbol

## 74LS393
designator U?
footprint DIP-14
part A pins: 1 CLK (in), 2 MR (in), 3 Q0 (out), 4 Q1 (out), 5 Q2 (out), 6 Q3 (out), 7 GND (power) hidden to GND, 14 VCC (power) hidden to VCC
part B pins: 7 GND (power) hidden to GND, 8 Q3 (out), 9 Q2 (out), 10 Q1 (out), 11 Q0 (out), 12 MR (in), 13 CLK (in), 14 VCC (power) hidden to VCC
2 alternate drawings of the same symbol

## 74LS395
designator U?
footprint DIP-14
pins: 1 ~{MR} (in), 2 DS (in), 3 P0 (in), 4 P1 (in), 5 P2 (in), 6 P3 (in), 7 S (in), 8 GND (power) hidden to GND, 9 ~{OE} (in), 10 CLK (in), 11 Q3 (hiz), 12 O3 (hiz), 13 O2 (hiz), 14 O1 (hiz), 15 O0 (hiz), 16 VCC (power) hidden to VCC
2 alternate drawings of the same symbol

## 74LS396
designator U?
footprint DIP-14
pins: 1 2Q1 (out), 2 1Q1 (out), 3 D1 (in), 4 2Q2 (out), 5 1Q2 (out), 6 D2 (in), 7 CLK (in), 8 GND (power) hidden to GND, 9 D3 (in), 10 1Q3 (out), 11 2Q3 (out), 12 D4 (in), 13 1Q4 (out), 14 2Q4 (out), 15 ~{G} (in), 16 VCC (power) hidden to VCC
2 alternate drawings of the same symbol

## 74LS398
designator U?
footprint DIP-20
pins: 1 WS (in), 2 QA (out), 3 ~{QA} (out), 4 A1 (in), 5 A2 (in), 6 B2 (in), 7 B1 (in), 8 ~{QB} (out), 9 QB (out), 10 GND (power) hidden to GND, 11 CLK (in), 12 QC (out), 13 ~{QC} (out), 14 C1 (in), 15 C2 (in), 16 D2 (in), 17 D1 (in), 18 ~{QD} (out), 19 QD (out), 20 VCC (power) hidden to VCC
2 alternate drawings of the same symbol

## 74LS399
designator U?
footprint DIP-16
pins: 1 WS (in), 2 QA (out), 3 A1 (in), 4 A2 (in), 5 B2 (in), 6 B1 (in), 7 QB (out), 8 GND (power) hidden to GND, 9 CLK (in), 10 QC (out), 11 C1 (in), 12 C2 (in), 13 D2 (in), 14 D1 (in), 15 QD (out), 16 VCC (power) hidden to VCC
2 alternate drawings of the same symbol

## 74LS440
designator U?
footprint DIP-20
pins: 1 CS (in), 2 B1 (io), 3 C1 (io), 4 C2 (io), 5 B2 (io), 6 B3 (io), 7 C3 (io), 8 C4 (io), 9 B4 (io), 10 GND (power) hidden to GND, 11 S0 (in), 12 S1 (in), 13 A4 (io), 14 A3 (io), 15 A2 (io), 16 A1 (io), 17 GA (in), 18 GB (in), 19 GC (in), 20 VCC (power) hidden to VCC
2 alternate drawings of the same symbol

## 74LS446
designator U?
footprint DIP-16
pins: 1 ~{G}BA (in), 2 A1 (io), 3 DR2 (in), 4 A2 (io), 5 A3 (io), 6 DR3 (in), 7 A4 (io), 8 GND (power) hidden to GND, 9 B4 (io), 10 DR4 (in), 11 B3 (io), 12 B1 (io), 12 B2 (io), 13 DR1 (in), 15 ~{G}AB (in), 16 VCC (power) hidden to VCC
2 alternate drawings of the same symbol

## 74LS449
designator U?
footprint DIP-16
pins: 1 ~{G}BA (in), 2 A1 (io), 3 DR2 (in), 4 A2 (io), 5 A3 (io), 6 DR3 (in), 7 A4 (io), 8 GND (power) hidden to GND, 9 B4 (io), 10 DR4 (in), 11 B3 (io), 12 B2 (io), 13 DR1 (in), 14 B1 (io), 15 ~{G}AB (in), 16 VCC (power) hidden to VCC
2 alternate drawings of the same symbol

## 74LS465
designator U?
footprint DIP-20
pins: 1 ~{G}1 (in), 2 D1 (in), 3 Q1 (hiz), 4 D2 (in), 5 Q2 (hiz), 6 D3 (in), 7 Q3 (hiz), 8 D4 (in), 9 Q4 (hiz), 10 GND (power) hidden to GND, 11 Q5 (hiz), 12 D5 (in), 13 Q6 (hiz), 14 D6 (in), 15 Q7 (hiz), 16 D7 (in), 17 Q8 (hiz), 18 D8 (in), 19 ~{G}2 (in), 20 VCC (power) hidden to VCC
2 alternate drawings of the same symbol

## 74LS466
designator U?
footprint DIP-20
pins: 1 ~{G}1 (in), 2 D1 (in), 3 Q1 (hiz), 4 D2 (in), 5 Q2 (hiz), 6 D3 (in), 7 Q3 (hiz), 8 D4 (in), 9 Q4 (hiz), 10 GND (power) hidden to GND, 11 Q5 (hiz), 12 D5 (in), 13 Q6 (hiz), 14 D6 (in), 15 Q7 (hiz), 16 D7 (in), 17 Q8 (hiz), 18 D8 (in), 19 ~{G}2 (in), 20 VCC (power) hidden to VCC
2 alternate drawings of the same symbol

## 74LS467
designator U?
footprint DIP-20
part A pins: 1 ~{G} (in), 2 D1 (in), 3 Q1 (hiz), 4 D2 (in), 5 Q2 (hiz), 6 D3 (in), 7 Q3 (hiz), 8 D4 (in), 9 Q4 (hiz), 10 GND (power) hidden to GND, 20 VCC (power) hidden to VCC
part B pins: 10 GND (power) hidden to GND, 11 Q1 (hiz), 12 D1 (in), 13 Q2 (hiz), 14 D2 (in), 15 Q3 (hiz), 16 D3 (in), 17 Q4 (hiz), 18 D4 (in), 19 ~{G} (in), 20 VCC (power) hidden to VCC
2 alternate drawings of the same symbol

## 74LS468
designator U?
footprint DIP-20
part A pins: 1 ~{G} (in), 2 D1 (in), 3 Q1 (hiz), 4 D2 (in), 5 Q2 (hiz), 6 D3 (in), 7 Q3 (hiz), 8 D4 (in), 9 Q4 (hiz), 10 GND (power) hidden to GND, 20 VCC (power) hidden to VCC
part B pins: 10 GND (power) hidden to GND, 11 Q1 (hiz), 12 D1 (in), 13 Q2 (hiz), 14 D2 (in), 15 Q3 (hiz), 16 D3 (in), 17 Q4 (hiz), 18 D4 (in), 19 ~{G} (in), 20 VCC (power) hidden to VCC
2 alternate drawings of the same symbol

## 74LS490
designator U?
footprint DIP-16
part A pins: 1 CLK (in), 2 MR (in), 3 Q0 (out), 4 MS (in), 5 Q1 (out), 6 Q2 (out), 7 Q3 (out), 8 GND (power) hidden to GND, 16 VCC (power) hidden to VCC
part B pins: 8 GND (power) hidden to GND, 9 Q3 (out), 10 Q2 (out), 11 Q1 (out), 12 MS (in), 13 Q0 (out), 14 MR (in), 15 CLK (in), 16 VCC (power) hidden to VCC
2 alternate drawings of the same symbol

## 74LS540
designator U?
footprint DIP-20
pins: 1 ~{E1} (in), 2 D1 (in), 3 D2 (in), 4 D3 (in), 5 D4 (in), 6 D5 (in), 7 D6 (in), 8 D7 (in), 9 D8 (in), 10 GND (power) hidden to GND, 11 Q8 (hiz), 12 Q7 (hiz), 13 Q6 (hiz), 14 Q5 (hiz), 15 Q4 (hiz), 16 Q3 (hiz), 17 Q2 (hiz), 18 Q1 (hiz), 19 ~{E2} (in), 20 VCC (power) hidden to VCC
2 alternate drawings of the same symbol

## 74LS541
designator U?
footprint DIP-20
pins: 1 ~{E1} (in), 2 D1 (in), 3 D2 (in), 4 D3 (in), 5 D4 (in), 6 D5 (in), 7 D6 (in), 8 D7 (in), 9 D8 (in), 10 GND (power) hidden to GND, 11 Q8 (hiz), 12 Q7 (hiz), 13 Q6 (hiz), 14 Q5 (hiz), 15 Q4 (hiz), 16 Q3 (hiz), 17 Q2 (hiz), 18 Q1 (hiz), 19 ~{E2} (in), 20 VCC (power) hidden to VCC
2 alternate drawings of the same symbol

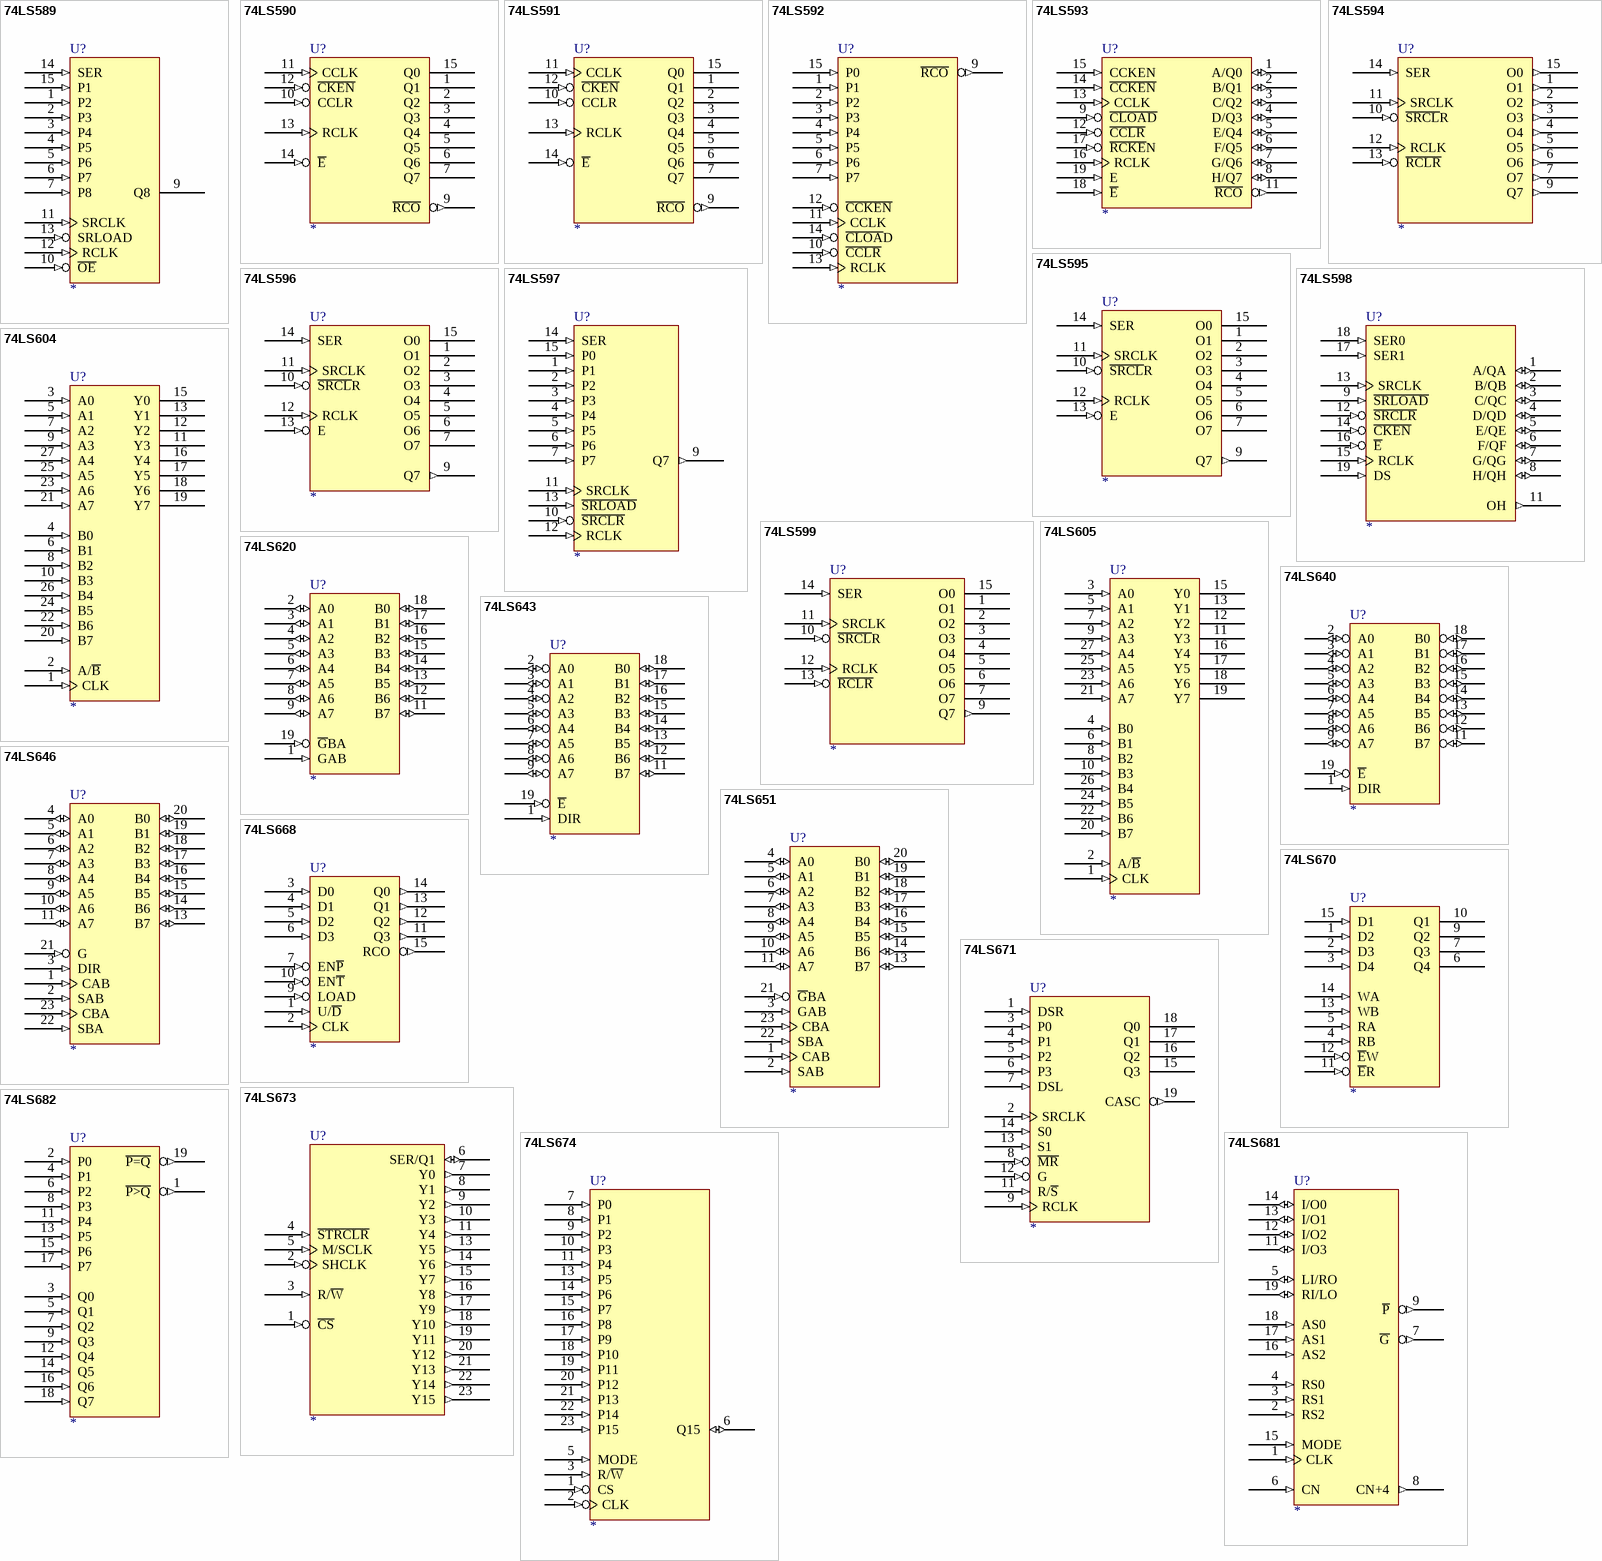
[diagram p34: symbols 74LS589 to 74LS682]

## 74LS589
designator U?
footprint DIP-16
pins: 1 P2 (in), 2 P3 (in), 3 P4 (in), 4 P5 (in), 5 P6 (in), 6 P7 (in), 7 P8 (in), 8 GND (power) hidden to GND, 9 Q8 (hiz), 10 ~{OE} (in), 11 SRCLK (in), 12 RCLK (in), 13 SRLOAD (in), 14 SER (in), 15 P1 (in), 16 VCC (power) hidden to VCC
2 alternate drawings of the same symbol

## 74LS590
designator U?
footprint DIP-16
pins: 1 Q1 (hiz), 2 Q2 (hiz), 3 Q3 (hiz), 4 Q4 (hiz), 5 Q5 (hiz), 6 Q6 (hiz), 7 Q7 (hiz), 8 GND (power) hidden to GND, 9 ~{RCO} (out), 10 CCLR (in), 11 CCLK (in), 12 ~{CKEN} (in), 13 RCLK (in), 14 ~{E} (in), 15 Q0 (hiz), 16 VCC (power) hidden to VCC
2 alternate drawings of the same symbol

## 74LS591
designator U?
footprint DIP-16
pins: 1 Q1 (oc), 2 Q2 (oc), 3 Q3 (oc), 4 Q4 (oc), 5 Q5 (oc), 6 Q6 (oc), 7 Q7 (oc), 8 GND (power) hidden to GND, 9 ~{RCO} (out), 10 CCLR (in), 11 CCLK (in), 12 ~{CKEN} (in), 13 RCLK (in), 14 ~{E} (in), 15 Q0 (oc), 16 VCC (power) hidden to VCC
2 alternate drawings of the same symbol

## 74LS592
designator U?
footprint DIP-16
pins: 1 P1 (in), 2 P2 (in), 3 P3 (in), 4 P4 (in), 5 P5 (in), 6 P6 (in), 7 P7 (in), 8 GND (power) hidden to GND, 9 ~{RCO} (out), 10 ~{CCLR} (in), 11 CCLK (in), 12 ~{CCKEN} (in), 13 RCLK (in), 14 ~{CLOA}D (in), 15 P0 (in), 16 VCC (power) hidden to VCC
2 alternate drawings of the same symbol

## 74LS593
designator U?
footprint DIP-20
pins: 1 A/Q0 (io), 2 B/Q1 (io), 3 C/Q2 (io), 4 D/Q3 (io), 5 E/Q4 (io), 6 F/Q5 (io), 7 G/Q6 (io), 8 H/Q7 (io), 9 ~{CLOAD} (in), 10 GND (power) hidden to GND, 11 ~{RCO} (out), 12 ~{CCLR} (in), 13 CCLK (in), 14 ~{CCKEN} (in), 15 CCKEN (in), 16 RCLK (in), 17 ~{RCKE}N (in), 18 ~{E} (in), 19 E (in), 20 VCC (power) hidden to VCC
2 alternate drawings of the same symbol

## 74LS594
designator U?
footprint DIP-16
pins: 1 O1 (out), 2 O2 (out), 3 O3 (out), 4 O4 (out), 5 O5 (out), 6 O6 (out), 7 O7 (out), 8 GND (power) hidden to GND, 9 Q7 (out), 10 ~{SRCL}R (in), 11 SRCLK (in), 12 RCLK (in), 13 ~{RCLR} (in), 14 SER (in), 15 O0 (out), 16 VCC (power) hidden to VCC
2 alternate drawings of the same symbol

## 74LS595
designator U?
footprint DIP-16
pins: 1 O1 (hiz), 2 O2 (hiz), 3 O3 (hiz), 4 O4 (hiz), 5 O5 (hiz), 6 O6 (hiz), 7 O7 (hiz), 8 GND (power) hidden to GND, 9 Q7 (out), 10 ~{SRCL}R (in), 11 SRCLK (in), 12 RCLK (in), 13 E (in), 14 SER (in), 15 O0 (hiz), 16 VCC (power) hidden to VCC
2 alternate drawings of the same symbol

## 74LS596
designator U?
footprint DIP-16
pins: 1 O1 (oc), 2 O2 (oc), 3 O3 (oc), 4 O4 (oc), 5 O5 (oc), 6 O6 (oc), 7 O7 (oc), 8 GND (power) hidden to GND, 9 Q7 (out), 10 ~{SRCL}R (in), 11 SRCLK (in), 12 RCLK (in), 13 E (in), 14 SER (in), 15 O0 (oc), 16 VCC (power) hidden to VCC
2 alternate drawings of the same symbol

## 74LS597
designator U?
footprint DIP-16
pins: 1 P1 (in), 2 P2 (in), 3 P3 (in), 4 P4 (in), 5 P5 (in), 6 P6 (in), 7 P7 (in), 8 GND (power) hidden to GND, 9 Q7 (out), 10 ~{SRCLR} (in), 11 SRCLK (in), 12 RCLK (in), 13 ~{SRLOAD} (in), 14 SER (in), 15 P0 (in), 16 VCC (power) hidden to VCC
2 alternate drawings of the same symbol

## 74LS598
designator U?
footprint DIP-20
pins: 1 A/QA (io), 2 B/QB (io), 3 C/QC (io), 4 D/QD (io), 5 E/QE (io), 6 F/QF (io), 7 G/QG (io), 8 H/QH (io), 9 ~{SRLOAD} (in), 10 GND (power) hidden to GND, 11 OH (out), 12 ~{SRCLR} (in), 13 SRCLK (in), 14 ~{CKEN} (in), 15 RCLK (in), 16 ~{E} (in), 17 SER1 (in), 18 SER0 (in), 19 DS (in), 20 VCC (power) hidden to VCC
2 alternate drawings of the same symbol

## 74LS599
designator U?
footprint DIP-16
pins: 1 O1 (oc), 2 O2 (oc), 3 O3 (oc), 4 O4 (oc), 5 O5 (oc), 6 O6 (oc), 7 O7 (oc), 8 GND (power) hidden to GND, 9 Q7 (out), 10 ~{SRCL}R (in), 11 SRCLK (in), 12 RCLK (in), 13 ~{RCLR} (in), 14 SER (in), 15 O0 (oc), 16 VCC (power) hidden to VCC
2 alternate drawings of the same symbol

## 74LS604
designator U?
footprint DIP-28
pins: 1 CLK (in), 2 A/~{B} (in), 3 A0 (in), 4 B0 (in), 5 A1 (in), 6 B1 (in), 7 A2 (in), 8 B2 (in), 9 A3 (in), 10 B3 (in), 11 Y3 (hiz), 12 Y2 (hiz), 13 Y1 (hiz), 14 GND (power) hidden to GND, 15 Y0 (hiz), 16 Y4 (hiz), 17 Y5 (hiz), 18 Y6 (hiz), 19 Y7 (hiz), 20 B7 (in), 21 A7 (in), 22 B6 (in), 23 A6 (in), 24 B5 (in), 25 A5 (in), 26 B4 (in), 27 A4 (in), 28 VCC (power) hidden to VCC
2 alternate drawings of the same symbol

## 74LS605
designator U?
footprint DIP-28
pins: 1 CLK (in), 2 A/~{B} (in), 3 A0 (in), 4 B0 (in), 5 A1 (in), 6 B1 (in), 7 A2 (in), 8 B2 (in), 9 A3 (in), 10 B3 (in), 11 Y3 (oc), 12 Y2 (oc), 13 Y1 (oc), 14 GND (power) hidden to GND, 15 Y0 (oc), 16 Y4 (oc), 17 Y5 (oc), 18 Y6 (oc), 19 Y7 (oc), 20 B7 (in), 21 A7 (in), 22 B6 (in), 23 A6 (in), 24 B5 (in), 25 A5 (in), 26 B4 (in), 27 A4 (in), 28 VCC (power) hidden to VCC
2 alternate drawings of the same symbol

## 74LS620
designator U?
footprint DIP-20
pins: 1 GAB (in), 2 A0 (io), 3 A1 (io), 4 A2 (io), 5 A3 (io), 6 A4 (io), 7 A5 (io), 8 A6 (io), 9 A7 (io), 10 GND (power) hidden to GND, 11 B7 (io), 12 B6 (io), 13 B5 (io), 14 B4 (io), 15 B3 (io), 16 B2 (io), 17 B1 (io), 18 B0 (io), 19 ~{G}BA (in), 20 VCC (power) hidden to VCC
2 alternate drawings of the same symbol

## 74LS640
designator U?
footprint DIP-20
pins: 1 DIR (in), 2 A0 (io), 3 A1 (io), 4 A2 (io), 5 A3 (io), 6 A4 (io), 7 A5 (io), 8 A6 (io), 9 A7 (io), 10 GND (power) hidden to GND, 11 B7 (io), 12 B6 (io), 13 B5 (io), 14 B4 (io), 15 B3 (io), 16 B2 (io), 17 B1 (io), 18 B0 (io), 19 ~{E} (in), 20 VCC (power) hidden to VCC
2 alternate drawings of the same symbol

## 74LS643
designator U?
footprint DIP-20
pins: 1 DIR (in), 2 A0 (io), 3 A1 (io), 4 A2 (io), 5 A3 (io), 6 A4 (io), 7 A5 (io), 8 A6 (io), 9 A7 (io), 10 GND (power) hidden to GND, 11 B7 (io), 12 B6 (io), 13 B5 (io), 14 B4 (io), 15 B3 (io), 16 B2 (io), 17 B1 (io), 18 B0 (io), 19 ~{E} (in), 20 VCC (power) hidden to VCC
2 alternate drawings of the same symbol

## 74LS646
designator U?
footprint DIP-24
pins: 1 CAB (in), 2 SAB (in), 3 DIR (in), 4 A0 (io), 5 A1 (io), 6 A2 (io), 7 A3 (io), 8 A4 (io), 9 A5 (io), 10 A6 (io), 11 A7 (io), 12 GND (power) hidden to GND, 13 B7 (io), 14 B6 (io), 15 B5 (io), 16 B4 (io), 17 B3 (io), 18 B2 (io), 19 B1 (io), 20 B0 (io), 21 G (in), 22 SBA (in), 23 CBA (in), 24 VCC (power) hidden to VCC
2 alternate drawings of the same symbol

## 74LS651
designator U?
footprint DIP-24
pins: 1 CAB (in), 2 SAB (in), 3 GAB (in), 4 A0 (io), 5 A1 (io), 6 A2 (io), 7 A3 (io), 8 A4 (io), 9 A5 (io), 10 A6 (io), 11 A7 (io), 12 GND (power) hidden to GND, 13 B7 (io), 14 B6 (io), 15 B5 (io), 16 B4 (io), 17 B3 (io), 18 B2 (io), 19 B1 (io), 20 B0 (io), 21 ~{G}BA (in), 22 SBA (in), 23 CBA (in), 24 VCC (power) hidden to VCC
2 alternate drawings of the same symbol

## 74LS668
designator U?
footprint DIP-16
pins: 1 U/~{D} (in), 2 CLK (in), 3 D0 (in), 4 D1 (in), 5 D2 (in), 6 D3 (in), 7 EN~{P} (in), 8 GND (power) hidden to GND, 9 LOAD (in), 10 EN~{T} (in), 11 Q3 (out), 12 Q2 (out), 13 Q1 (out), 14 Q0 (out), 15 RCO (out), 16 VCC (power) hidden to VCC
2 alternate drawings of the same symbol

## 74LS670
designator U?
footprint DIP-16
pins: 1 D2 (in), 2 D3 (in), 3 D4 (in), 4 RB (in), 5 RA (in), 6 Q4 (hiz), 7 Q3 (hiz), 8 GND (power) hidden to GND, 9 Q2 (hiz), 10 Q1 (hiz), 11 ~{E}R (in), 12 ~{E}W (in), 13 WB (in), 14 WA (in), 15 D1 (in), 16 VCC (power) hidden to VCC
2 alternate drawings of the same symbol

## 74LS671
designator U?
footprint DIP-20
pins: 1 DSR (in), 2 SRCLK (in), 3 P0 (in), 4 P1 (in), 5 P2 (in), 6 P3 (in), 7 DSL (in), 8 ~{MR} (in), 9 RCLK (in), 10 GND (power) hidden to GND, 11 R/~{S} (in), 12 G (in), 13 S1 (in), 14 S0 (in), 15 Q3 (hiz), 16 Q2 (hiz), 17 Q1 (hiz), 18 Q0 (hiz), 19 CASC (out), 20 VCC (power) hidden to VCC
2 alternate drawings of the same symbol

## 74LS673
designator U?
footprint DIP-24
pins: 1 ~{CS} (in), 2 SHCLK (in), 3 R/~{W} (in), 4 ~{STRCLR} (in), 5 M/SCLK (in), 6 SER/Q1 (io), 7 Y0 (out), 8 Y1 (out), 9 Y2 (out), 10 Y3 (out), 11 Y4 (out), 12 GND (power) hidden to GND, 13 Y5 (out), 14 Y6 (out), 15 Y7 (out), 16 Y8 (out), 17 Y9 (out), 18 Y10 (out), 19 Y11 (out), 20 Y12 (out), 21 Y13 (out), 22 Y14 (out), 23 Y15 (out), 24 VCC (power) hidden to VCC
2 alternate drawings of the same symbol

## 74LS674
designator U?
footprint DIP-24
pins: 1 CS (in), 2 CLK (in), 3 R/~{W} (in), 5 MODE (in), 6 Q15 (io), 7 P0 (in), 8 P1 (in), 9 P2 (in), 10 P3 (in), 11 P4 (in), 12 GND (power) hidden to GND, 13 P5 (in), 14 P6 (in), 15 P7 (in), 16 P8 (in), 17 P9 (in), 18 P10 (in), 19 P11 (in), 20 P12 (in), 21 P13 (in), 22 P14 (in), 23 P15 (in), 24 VCC (power) hidden to VCC
2 alternate drawings of the same symbol

## 74LS681
designator U?
footprint DIP-20
pins: 1 CLK (in), 2 RS2 (in), 3 RS1 (in), 4 RS0 (in), 5 LI/RO (io), 6 CN (in), 7 ~{G} (out), 8 CN+4 (out), 9 ~{P} (out), 10 GND (power) hidden to GND, 11 I/O3 (io), 12 I/O2 (io), 13 I/O1 (io), 14 I/O0 (io), 15 MODE (in), 16 AS2 (in), 17 AS1 (in), 18 AS0 (in), 19 RI/LO (io), 20 VCC (power) hidden to VCC
2 alternate drawings of the same symbol

## 74LS682
designator U?
footprint DIP-20
pins: 1 ~{P>Q} (out), 2 P0 (in), 3 Q0 (in), 4 P1 (in), 5 Q1 (in), 6 P2 (in), 7 Q2 (in), 8 P3 (in), 9 Q3 (in), 10 GND (power) hidden to GND, 11 P4 (in), 12 Q4 (in), 13 P5 (in), 14 Q5 (in), 15 P6 (in), 16 Q6 (in), 17 P7 (in), 18 Q7 (in), 19 ~{P=Q} (out), 20 VCC (power) hidden to VCC
2 alternate drawings of the same symbol

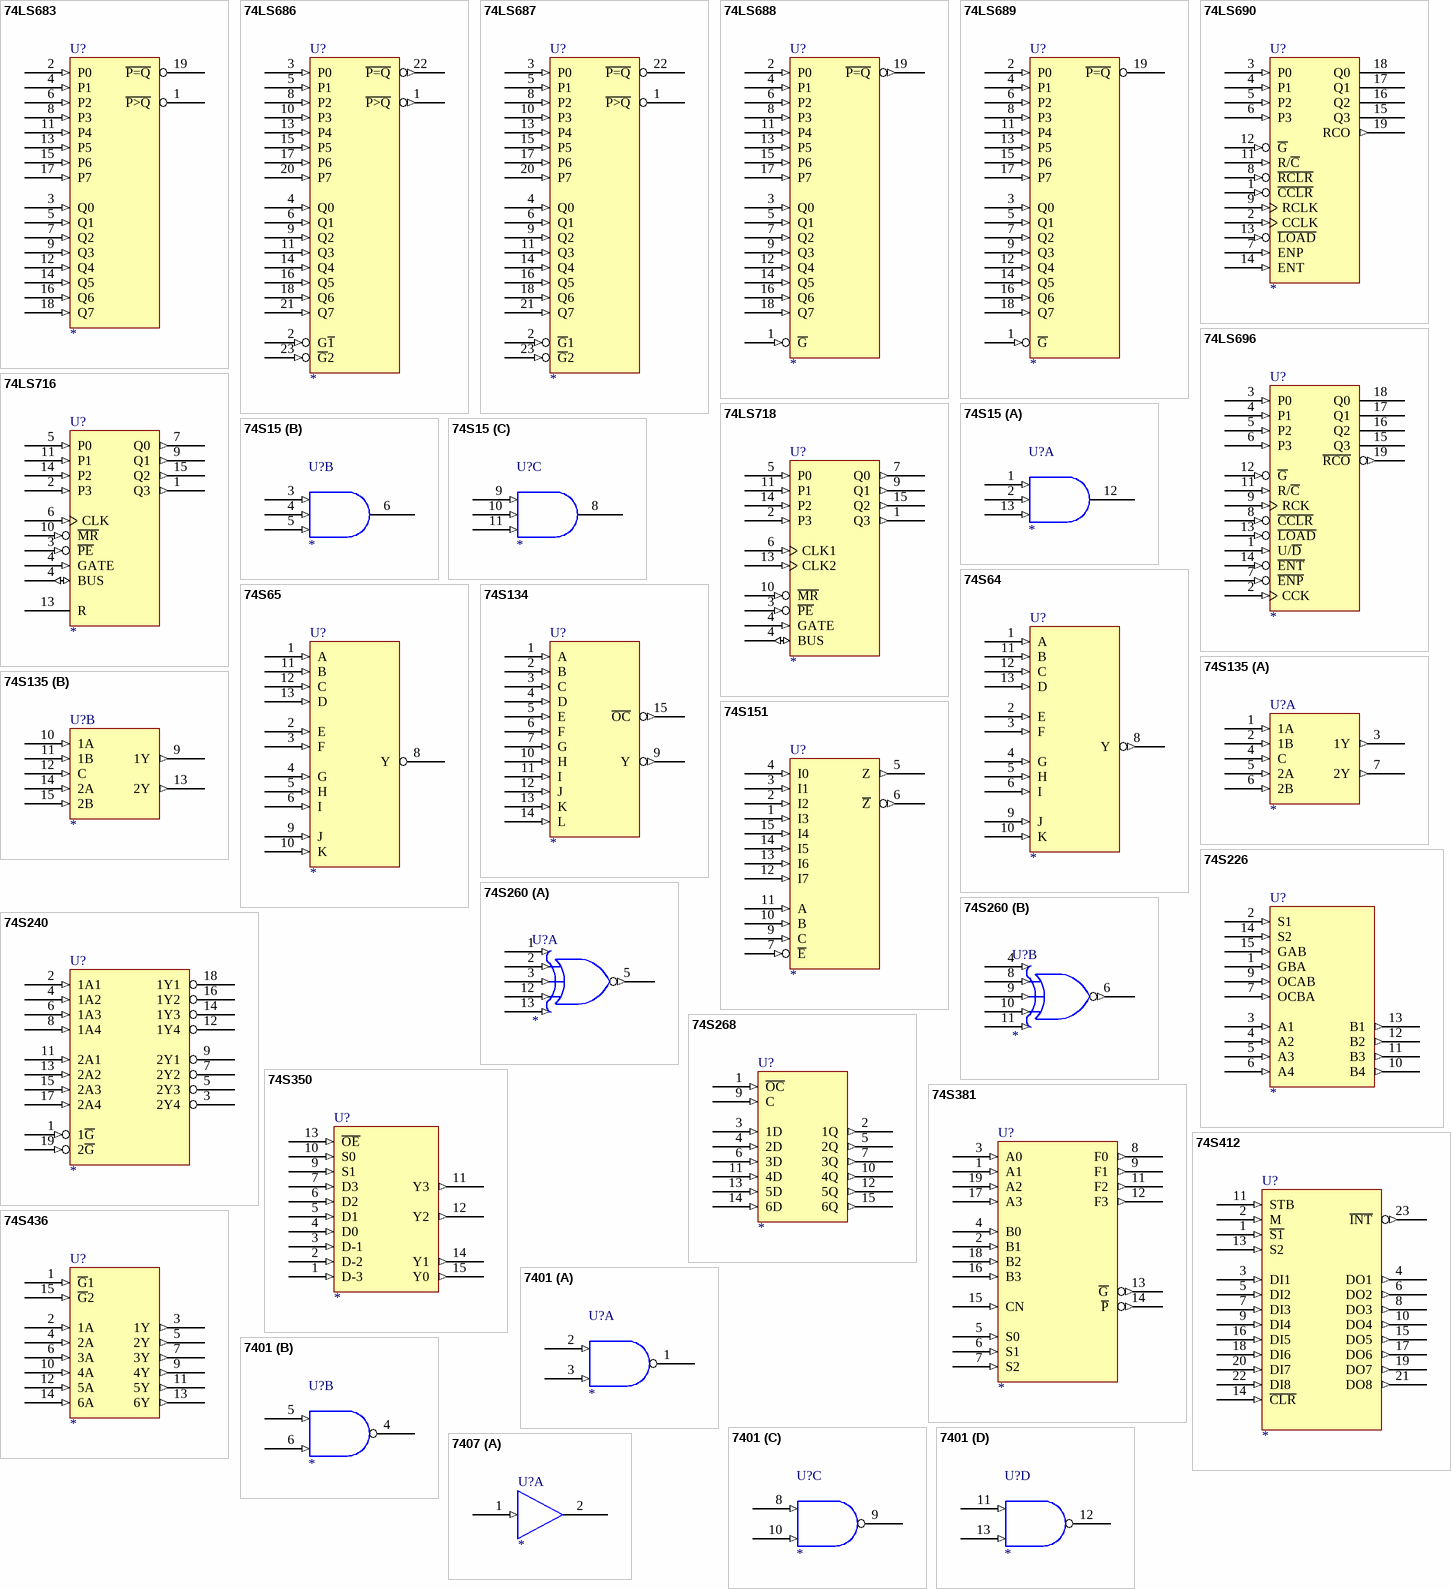
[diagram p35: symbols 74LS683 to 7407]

## 74LS683
designator U?
footprint DIP-20
pins: 1 ~{P>Q} (oc), 2 P0 (in), 3 Q0 (in), 4 P1 (in), 5 Q1 (in), 6 P2 (in), 7 Q2 (in), 8 P3 (in), 9 Q3 (in), 10 GND (power) hidden to GND, 11 P4 (in), 12 Q4 (in), 13 P5 (in), 14 Q5 (in), 15 P6 (in), 16 Q6 (in), 17 P7 (in), 18 Q7 (in), 19 ~{P=Q} (oc), 20 VCC (power) hidden to VCC
2 alternate drawings of the same symbol

## 74LS686
designator U?
footprint DIP-24
pins: 1 ~{P>Q} (out), 2 G~{1} (in), 3 P0 (in), 4 Q0 (in), 5 P1 (in), 6 Q1 (in), 8 P2 (in), 9 Q2 (in), 10 P3 (in), 11 Q3 (in), 12 GND (power) hidden to GND, 13 P4 (in), 14 Q4 (in), 15 P5 (in), 16 Q5 (in), 17 P6 (in), 18 Q6 (in), 20 P7 (in), 21 Q7 (in), 22 ~{P=Q} (out), 23 ~{G}2 (in), 24 VCC (power) hidden to VCC
2 alternate drawings of the same symbol

## 74LS687
designator U?
footprint DIP-24
pins: 1 ~{P>Q} (oc), 2 ~{G}1 (in), 3 P0 (in), 4 Q0 (in), 5 P1 (in), 6 Q1 (in), 8 P2 (in), 9 Q2 (in), 10 P3 (in), 11 Q3 (in), 12 GND (power) hidden to GND, 13 P4 (in), 14 Q4 (in), 15 P5 (in), 16 Q5 (in), 17 P6 (in), 18 Q6 (in), 20 P7 (in), 21 Q7 (in), 22 ~{P=Q} (oc), 23 ~{G}2 (in), 24 VCC (power) hidden to VCC
2 alternate drawings of the same symbol

## 74LS688
designator U?
footprint DIP-20
pins: 1 ~{G} (in), 2 P0 (in), 3 Q0 (in), 4 P1 (in), 5 Q1 (in), 6 P2 (in), 7 Q2 (in), 8 P3 (in), 9 Q3 (in), 10 GND (power) hidden to GND, 11 P4 (in), 12 Q4 (in), 13 P5 (in), 14 Q5 (in), 15 P6 (in), 16 Q6 (in), 17 P7 (in), 18 Q7 (in), 19 ~{P=Q} (out), 20 VCC (power) hidden to VCC
2 alternate drawings of the same symbol

## 74LS689
designator U?
footprint DIP-20
pins: 1 ~{G} (in), 2 P0 (in), 3 Q0 (in), 4 P1 (in), 5 Q1 (in), 6 P2 (in), 7 Q2 (in), 8 P3 (in), 9 Q3 (in), 10 GND (power) hidden to GND, 11 P4 (in), 12 Q4 (in), 13 P5 (in), 14 Q5 (in), 15 P6 (in), 16 Q6 (in), 17 P7 (in), 18 Q7 (in), 19 ~{P=Q} (oc), 20 VCC (power) hidden to VCC
2 alternate drawings of the same symbol

## 74LS690
designator U?
footprint DIP-20
pins: 1 ~{CCLR} (in), 2 CCLK (in), 3 P0 (in), 4 P1 (in), 5 P2 (in), 6 P3 (in), 7 ENP (in), 8 ~{RCLR} (in), 9 RCLK (in), 10 GND (power) hidden to GND, 11 R/~{C} (in), 12 ~{G} (in), 13 ~{LOAD} (in), 14 ENT (in), 15 Q3 (hiz), 16 Q2 (hiz), 17 Q1 (hiz), 18 Q0 (hiz), 19 RCO (out), 20 VCC (power) hidden to VCC
2 alternate drawings of the same symbol

## 74LS696
designator U?
footprint DIP-20
pins: 1 U/~{D} (in), 2 CCK (in), 3 P0 (in), 4 P1 (in), 5 P2 (in), 6 P3 (in), 7 ~{ENP} (in), 8 ~{CCLR} (in), 9 RCK (in), 10 GND (power) hidden to GND, 11 R/~{C} (in), 12 ~{G} (in), 13 ~{LOAD} (in), 14 ~{ENT} (in), 15 Q3 (hiz), 16 Q2 (hiz), 17 Q1 (hiz), 18 Q0 (hiz), 19 ~{RCO} (out), 20 VCC (power) hidden to VCC
2 alternate drawings of the same symbol

## 74LS716
designator U?
footprint DIP-16
pins: 1 Q3 (out), 2 P3 (in), 3 ~{PE} (in), 4 GATE (in), 4 BUS (io), 5 P0 (in), 6 CLK (in), 7 Q0 (out), 8 GND (power) hidden to GND, 9 Q1 (out), 10 ~{MR} (in), 11 P1 (in), 13 R, 14 P2 (in), 15 Q2 (out), 16 VCC (power) hidden to VCC
2 alternate drawings of the same symbol

## 74LS718
designator U?
footprint DIP-16
pins: 1 Q3 (out), 2 P3 (in), 3 ~{PE} (in), 4 GATE (in), 4 BUS (io), 5 P0 (in), 6 CLK1 (in), 7 Q0 (out), 8 GND (power) hidden to GND, 9 Q1 (out), 10 ~{MR} (in), 11 P1 (in), 13 CLK2 (in), 14 P2 (in), 15 Q2 (out), 16 VCC (power) hidden to VCC
2 alternate drawings of the same symbol

## 74S15
designator U?
footprint DIP-14
part A pins: 1 (in), 2 (in), 7 GND (power) hidden to GND, 12 (oc), 13 (in), 14 VCC (power) hidden to VCC
part B pins: 3 (in), 4 (in), 5 (in), 6 (oc), 7 GND (power) hidden to GND, 14 VCC (power) hidden to VCC
part C pins: 7 GND (power) hidden to GND, 8 (oc), 9 (in), 10 (in), 11 (in), 14 VCC (power) hidden to VCC
2 alternate drawings of the same symbol

## 74S64
designator U?
footprint DIP-14
pins: 1 A (in), 2 E (in), 3 F (in), 4 G (in), 5 H (in), 6 I (in), 7 GND (power) hidden to GND, 8 Y (out), 9 J (in), 10 K (in), 11 B (in), 12 C (in), 13 D (in), 14 VCC (power) hidden to VCC
2 alternate drawings of the same symbol

## 74S65
designator U?
footprint DIP-14
pins: 1 A (in), 2 E (in), 3 F (in), 4 G (in), 5 H (in), 6 I (in), 7 GND (power) hidden to GND, 8 Y (oc), 9 J (in), 10 K (in), 11 B (in), 12 C (in), 13 D (in), 14 VCC (power) hidden to VCC
2 alternate drawings of the same symbol

## 74S134
designator U?
footprint DIP-16
pins: 1 A (in), 2 B (in), 3 C (in), 4 D (in), 5 E (in), 6 F (in), 7 G (in), 8 GND (power) hidden to GND, 9 Y (out), 10 H (in), 11 I (in), 12 J (in), 13 K (in), 14 L (in), 15 ~{OC} (out), 16 VCC (power) hidden to VCC
2 alternate drawings of the same symbol

## 74S135
designator U?
footprint DIP-16
part A pins: 1 1A (in), 2 1B (in), 3 1Y (out), 4 C (in), 5 2A (in), 6 2B (in), 7 2Y (out), 8 GND (power) hidden to GND, 16 VCC (power) hidden to VCC
part B pins: 8 GND (power) hidden to GND, 9 1Y (out), 10 1A (in), 11 1B (in), 12 C (in), 13 2Y (out), 14 2A (in), 15 2B (in), 16 VCC (power) hidden to VCC
2 alternate drawings of the same symbol

## 74S151
designator U?
footprint DIP-16
pins: 1 I3 (in), 2 I2 (in), 3 I1 (in), 4 I0 (in), 5 Z (out), 6 ~{Z} (out), 7 ~{E} (in), 8 GND (power) hidden to GND, 9 C (in), 10 B (in), 11 A (in), 12 I7 (in), 13 I6 (in), 14 I5 (in), 15 I4 (in), 16 VCC (power) hidden to VCC
2 alternate drawings of the same symbol

## 74S226
designator U?
footprint DIP-16
pins: 1 GBA (in), 2 S1 (in), 3 A1 (in), 4 A2 (in), 5 A3 (in), 6 A4 (in), 7 OCBA (in), 8 GND (power) hidden to GND, 9 OCAB (in), 10 B4 (out), 11 B3 (out), 12 B2 (out), 13 B1 (out), 14 S2 (in), 15 GAB (in), 16 VCC (power) hidden to VCC
2 alternate drawings of the same symbol

## 74S240
designator U?
footprint DIP-20
pins: 1 1~{G} (in), 2 1A1 (in), 3 2Y4 (hiz), 4 1A2 (in), 5 2Y3 (hiz), 6 1A3 (in), 7 2Y2 (hiz), 8 1A4 (in), 9 2Y1 (hiz), 10 GND (power) hidden to GND, 11 2A1 (in), 12 1Y4 (hiz), 13 2A2 (in), 14 1Y3 (hiz), 15 2A3 (in), 16 1Y2 (hiz), 17 2A4 (in), 18 1Y1 (hiz), 19 2~{G} (in), 20 VCC (power) hidden to VCC
2 alternate drawings of the same symbol

## 74S260
designator U?
footprint DIP-14
part A pins: 1 (in), 2 (in), 3 (in), 5 (out), 7 GND (power) hidden to GND, 12 (in), 13 (in), 14 VCC (power) hidden to VCC
part B pins: 4 (in), 6 (out), 7 GND (power) hidden to GND, 8 (in), 9 (in), 10 (in), 11 (in), 14 VCC (power) hidden to VCC
2 alternate drawings of the same symbol

## 74S268
designator U?
footprint DIP-16
pins: 1 ~{OC} (in), 2 1Q (out), 3 1D (in), 4 2D (in), 5 2Q (out), 6 3D (in), 7 3Q (out), 8 GND (power) hidden to GND, 9 C (in), 10 4Q (out), 11 4D (in), 12 5Q (out), 13 5D (in), 14 6D (in), 15 6Q (out), 16 VCC (power) hidden to VCC
2 alternate drawings of the same symbol

## 74S350
designator U?
footprint DIP-16
pins: 1 D-3 (in), 2 D-2 (in), 3 D-1 (in), 4 D0 (in), 5 D1 (in), 6 D2 (in), 7 D3 (in), 8 GND (power) hidden to GND, 9 S1 (in), 10 S0 (in), 11 Y3 (out), 12 Y2 (out), 13 ~{OE} (in), 14 Y1 (out), 15 Y0 (out), 16 VCC (power) hidden to VCC
2 alternate drawings of the same symbol

## 74S381
designator U?
footprint DIP-20
pins: 1 A1 (in), 2 B1 (in), 3 A0 (in), 4 B0 (in), 5 S0 (in), 6 S1 (in), 7 S2 (in), 8 F0 (out), 9 F1 (out), 10 GND (power) hidden to GND, 11 F2 (out), 12 F3 (out), 13 ~{G} (out), 14 ~{P} (out), 15 CN (in), 16 B3 (in), 17 A3 (in), 18 B2 (in), 19 A2 (in), 20 VCC (power) hidden to VCC
2 alternate drawings of the same symbol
